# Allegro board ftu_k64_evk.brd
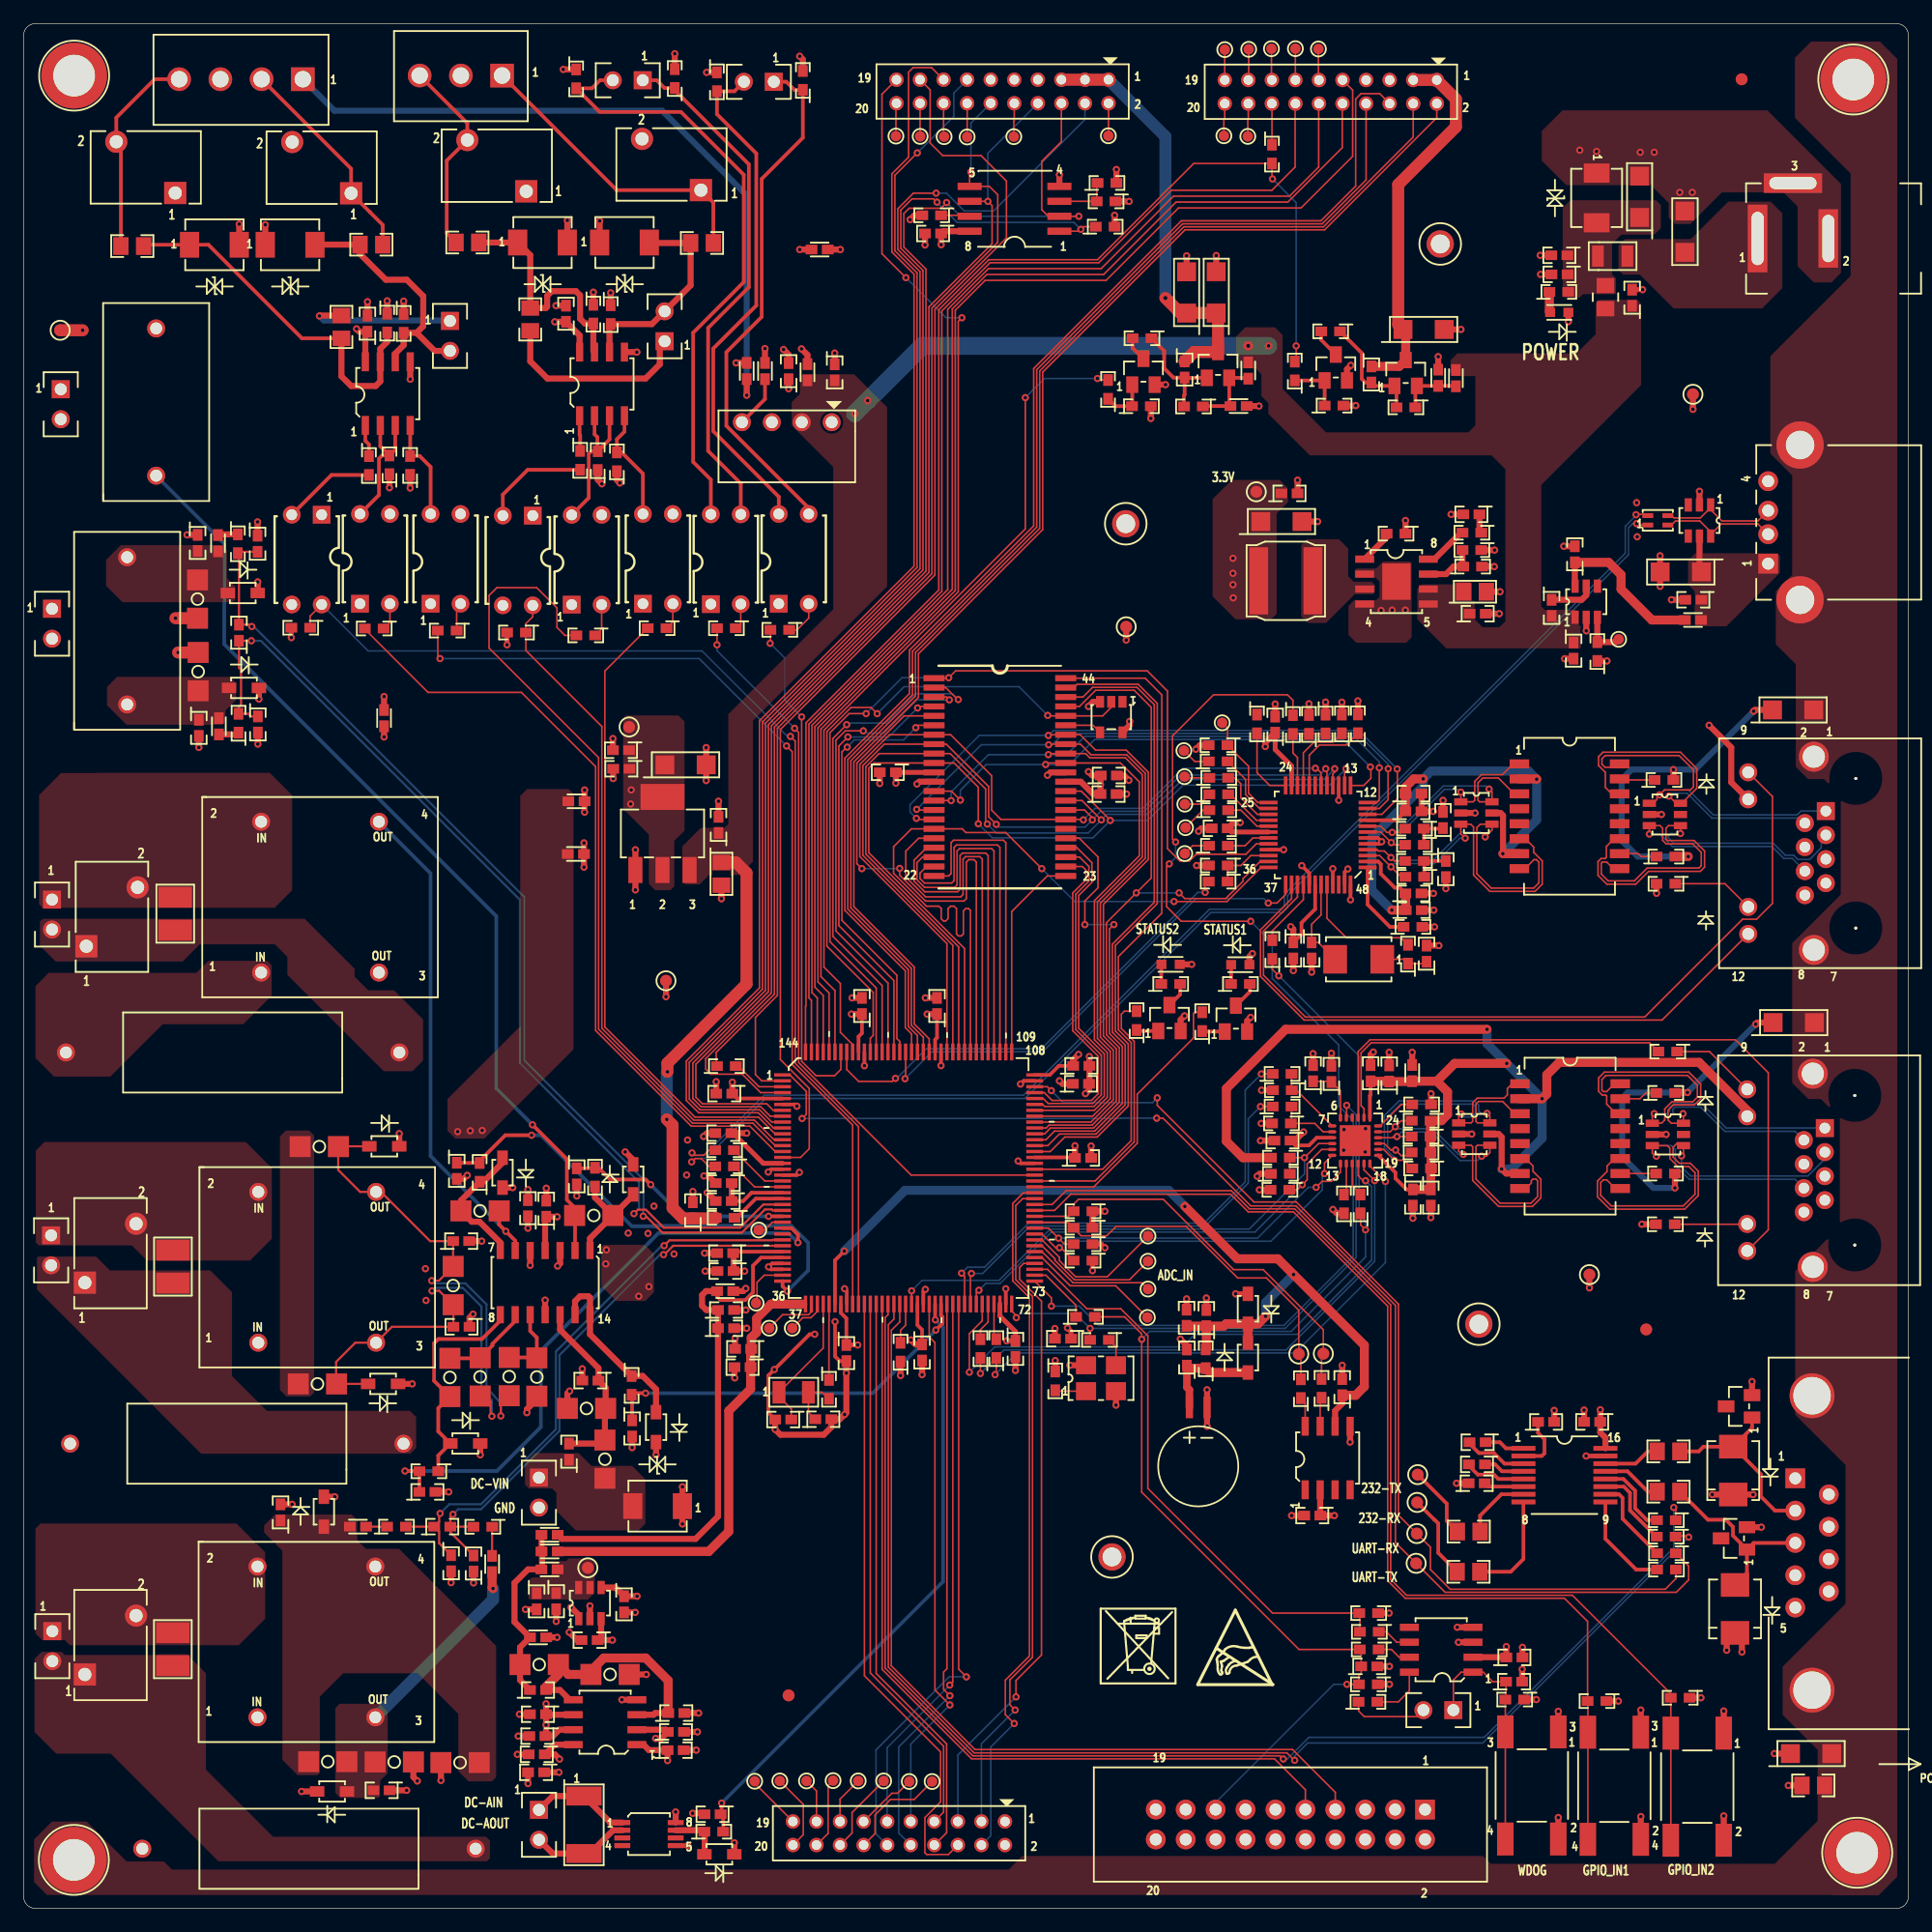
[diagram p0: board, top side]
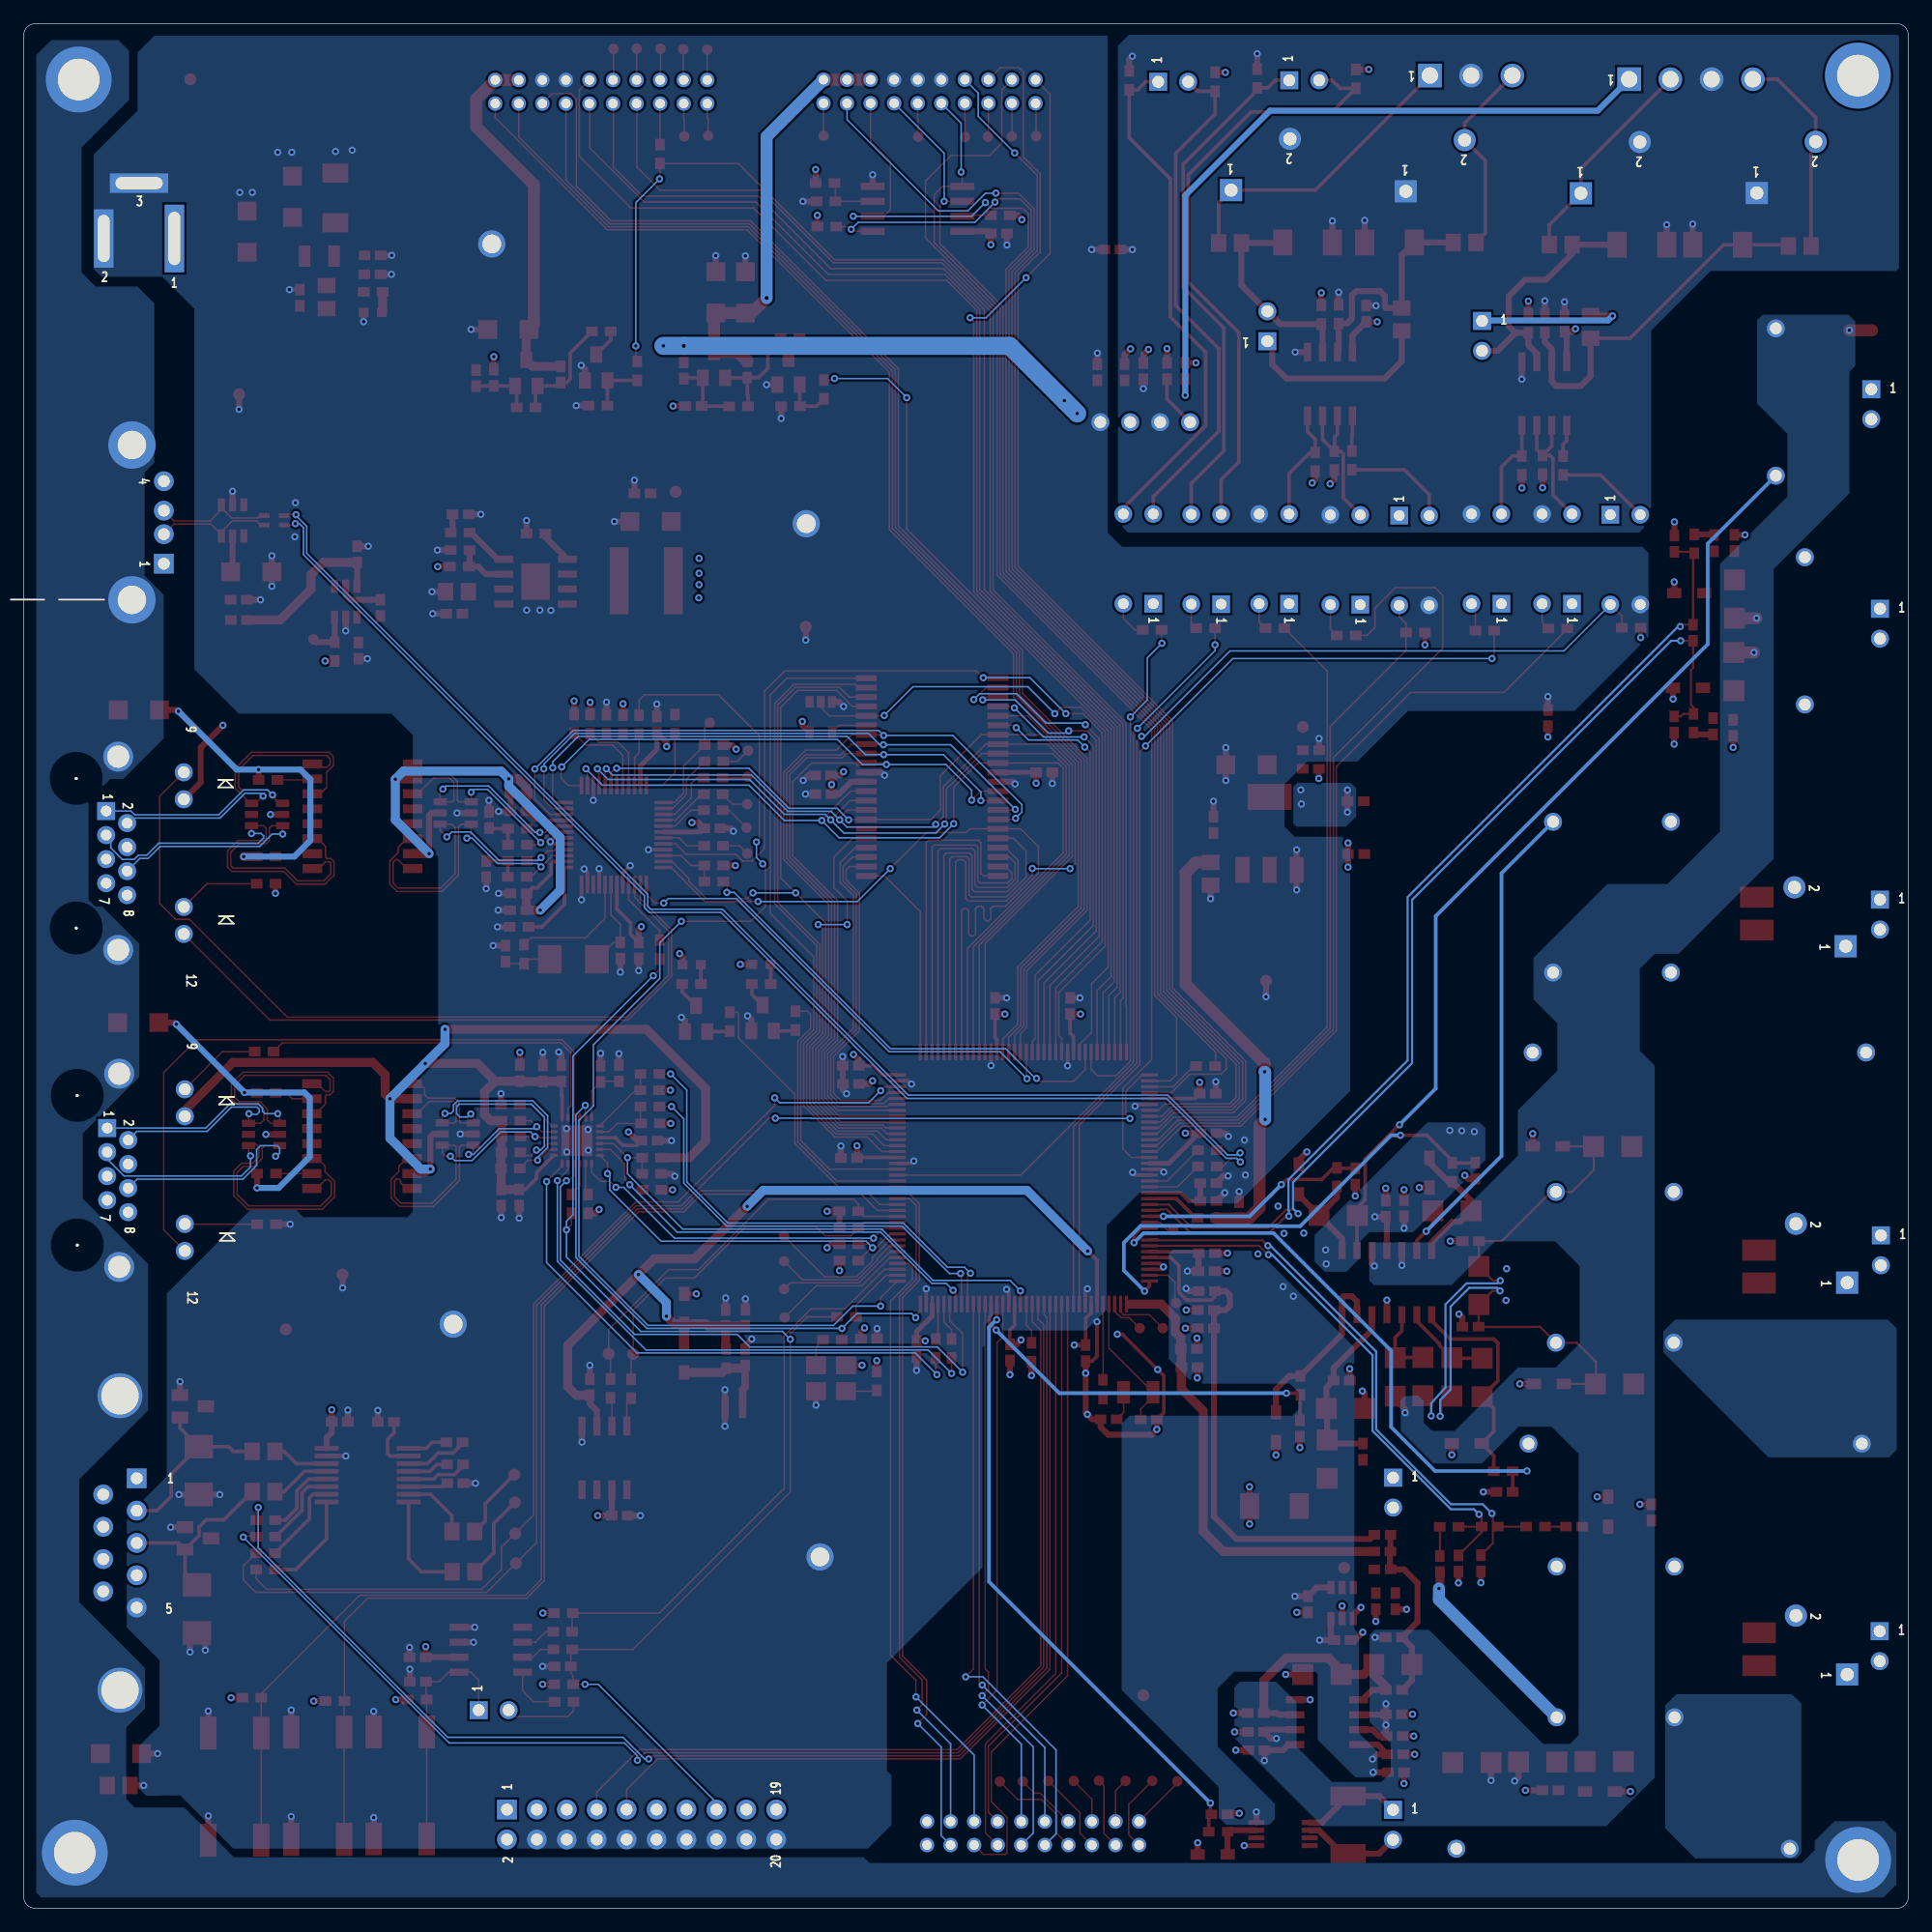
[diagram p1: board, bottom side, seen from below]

Outline 160 x 160 mm; copper layers: TOP, VCC, GND, BOTTOM. Coordinates in mm from the lower left corner of the outline.
Outline path: 0,158.98 0,1.02 arc(0.3,0.3) 1.02,0 158.98,0 arc(159.7,0.3) 160,1.02 160,158.98 arc(159.7,159.7) 158.98,160 1.02,160 arc(0.3,159.7) 0,158.98

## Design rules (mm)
net group AGND: nets N16923020 N16923054
net group DEBUG_RX: nets DEBUG_RX N16758843
net group DEBUG_TX: nets DEBUG_TX N16758837
net group DIFFPAIR0: nets ETH2_TXN ETH2_TXP
net group DIFFPAIR1: nets ETH2_RXN ETH2_RXP
net group DIFFPAIR2: nets ETH1_TXN ETH1_TXP
net group DIFFPAIR3: nets ETH1_RXN ETH1_RXP
net group DIFFPAIR4: nets ENET2_TX+ ENET2_TX-
net group DIFFPAIR5: nets ENET2_RX+ ENET2_RX-
net group DIFFPAIR6: nets ENET1_TX+ ENET1_TX-
net group DIFFPAIR7: nets ENET1_RX+ ENET1_RX-
net group DIFFPAIR8: nets USB_HOST_D_N USB_HOST_D_P
net group DIFFPAIR9: nets I2A_N I2A_P
net group DIFFPAIR11: nets U2_IN_L U2_IN_N
net group ENET_3V3A: nets ENET_3V3A RMII0_RXER
net group GPRS_PWR_CNTL: nets GPRS_PWR_CNTL N17042189
net group N16852593: nets N16852593 N16964483
net group RESET_B: nets N16852627 RESET_B
net group UART1_RX: nets N16997663 UART1_RX
net group UART1_TX: nets N16997666 UART1_TX
net group WDOG: nets N16852920 WDOG

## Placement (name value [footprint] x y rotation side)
BT1  MS621  [BAT_621]  99.71 40.93 180 top
C1  4.7UF  [CC0603]  89.76 70 0 top
C2  0.1UF  [CC0603]  77.54 76.61 90 top
C3  0.1UF  [CC0603]  71.17 76.61 90 top
C4  0.1UF  [CC0603]  89.94 63.7 0 top
C5  0.1UF  [CC0603]  59.48 69.16 180 top
C6  0.1UF  [CC0603]  69.84 47.14 270 top
C7  0.1UF  [CC0603]  59.41 65.81 180 top
C8  0.1UF  [CC0603]  89.78 71.53 0 top
C9  0.1UF  [CC0603]  76.27 47.19 270 top
C10  0.1UF  [CC0603]  84.2 47.5 270 top
C11  0.1UF  [CC0603]  61.08 47.5 180 top
C12  1.0UF  [CC0603]  61.03 45.95 180 top
C13  0.1UF  [CC0603]  59.63 49.25 0 top
C14  1.0UF  [CC0603]  59.63 50.8 0 top
C15  0.1UF  [CC0603]  59.56 55.63 180 top
C16  1.0UF  [CC0603]  59.58 54.1 180 top
C17  0.1UF  [CC0603]  59.43 61.57 180 top
C18  1.0UF  [CC0603]  59.43 60.05 180 top
C19  0.1UF  [CC0603]  56.81 59.26 90 top
C20  5.6PF  [CC0603]  64.49 41.5 180 top
C21  5.6PF  [CC0603]  67.89 41.53 0 top
C22  0.1UF  [CC0603]  109.39 33.35 180 top
C23  0.1UF  [CC0603]  111.93 44.25 90 top
C24  1.0UF  [CC0603]  100.4 50.11 90 top
C25  0.1UF  [CC0603]  98.72 50.14 90 top
C26  0.1UF  [CC0603]  88.23 48.36 180 top
C27  0.1UF  [CC0603]  98.75 46.76 90 top
C28  4.7UF  [CC0603]  73.36 96.44 180 top
C29  0.1UF  [CC0603]  92.1 94.6 0 top
C30  0.1UF  [CC0603]  92.13 96.17 0 top
C31  0.1UF  [CC0603]  77.21 142.18 180 top
C32  1.0UF  [CC0603]  44.37 59.4 90 top
C33  0.1UF  [CC0603]  42.81 59.44 90 top
C34  3300PF  [CC0603]  46.96 62.14 270 top
C35  0.01UF  [CC0603]  14.88 100.22 270 top
C36  3300PF  [CC0603]  19.89 100.5 270 top
C37  1000PF  [CC0603]  18.28 108.29 90 top
C38  0.01UF  [CC0603]  14.78 115.91 270 top
C39  3300PF  [CC0603]  36.77 62.61 270 top
C40  3300PF  [CC0603]  19.86 115.84 270 top
C41  4700pF  [CC1210]  12.87 84.44 90 top
C42  3300PF  [CC0603]  34.28 35.36 0 top
C43  0.01UF  [CC0603]  37.15 56.65 0 top
C44  4700pF  [CC1210]  12.68 54.48 90 top
C45  0.01UF  [CC0603]  37.17 49.37 180 top
C46  0.01UF  [CC0603]  46.3 38.77 90 top
C47  0.01UF  [CC0603]  48.11 44.81 180 top
C48  3300PF  [CC0603]  51.66 40.75 270 top
C49  0.01UF  [CC0603]  21.81 33.62 90 top
C50  3300PF  [CC0603]  36.29 29.3 270 top
C51  4700pF  [CC1210]  12.67 22.01 90 top
C52  1000PF  [CC0603]  35.54 32.41 0 top
C53  0.01UF  [CC0603]  30.39 10.03 180 top
C54  3300PF  [CC0603]  38.2 29.28 90 top
C55  3300PF  [CC0603]  58.49 7.99 180 top
C56  1.0UF  [CC0603]  50.97 25.82 270 top
C57  0.1UF  [CC0603]  48.05 22.78 180 top
C58  1.0UF  [CC0603]  43.55 26.07 270 top
C59  0.1UF  [CC0603]  45.21 26.08 270 top
C60  4.7UF  [CC0603]  115.92 70.88 90 top
C61  0.1UF  [CC0603]  119.46 60.35 270 top
C62  0.1UF  [CC0603]  106.87 65.18 180 top
C63  0.1UF  [CC0603]  117.93 60.35 270 top
C64  0.1UF  [CC0603]  114.35 70.9 90 top
C65  1000PF  [CC1206]  150.26 75.2 0 top
C66  1000PF  [CC1206]  151.73 13.14 0 top
C67  1.0UF  [CC0603]  111.02 70.84 90 top
C68  0.1UF  [CC0603]  109.46 70.9 90 top
C69  4.7UF  [CC0603]  107.79 81.32 270 top
C70  0.1UF  [CC0603]  106.24 100.49 90 top
C71  0.1UF  [CC0603]  101.54 91.69 180 top
C72  4.7UF  [CC0603]  117.99 94.63 0 top
C73  0.1UF  [CC0603]  117.98 93.12 0 top
C74  0.1UF  [CC0603]  118.01 84.74 0 top
C75  0.1UF  [CC0603]  117.98 86.16 0 top
C76  1000PF  [CC1206]  150.21 101.74 0 top
C77  8PF  [CC0603]  119.1 81.05 90 top
C78  8PF  [CC0603]  109.34 81.32 270 top
C80  100uF  [CC1206]  140.67 113.45 180 top
C81  2.2uF  [CC0603]  141.74 111.09 180 top
C82  2.2uF  [CC0603]  131.58 106.77 270 top
C83  1000PF  [CC0603]  129.71 110.4 270 top
C84  2.2uF  [CC0603]  131.68 114.95 90 top
C85  0.1UF  [CC0603]  29.19 134.53 90 top
C86  0.1UF  [CC0603]  68.85 130.39 270 top
C87  0.1UF  [CC0603]  64.94 130.49 90 top
C88  0.1UF  [CC0603]  46.05 135.37 90 top
C89  0.1UF  [CC0603]  129.24 41.3 0 top
C90  0.1UF  [CC0603]  133.15 41.3 180 top
C91  0.1UF  [CC0603]  123.35 36.09 0 top
C92  0.1UF  [CC0603]  123.38 37.69 180 top
C93  0.1UF  [CC0603]  123.43 39.57 180 top
C95  0.1UF  [CC0603]  126.52 19.25 0 top
C96  0.1UF  [CC0603]  126.55 21.31 0 top
C97  0.1UF  [CC0603]  114.23 20.55 0 top
C98  100uF  [CC1206]  98.73 137.18 90 top
C99  100uF  [CC1206]  101.24 137.18 90 top
C100  0.1UF  [CC0603]  98.56 130.63 270 top
C101  100uF  [CC1206]  118.84 134.03 0 top
C102  0.1UF  [CC0603]  114.41 130.21 270 top
C103  100uF  [CC1206]  137.18 145.3 90 top
C104  1.0UF  [CC0603]  130.38 138.71 180 top
C105  0.1UF  [CC0603]  130.37 140.33 180 top
C106  0.1UF  [CC0603]  136.55 136.73 90 top
C107  10UF  [CC0805]  123.21 111.77 0 top
C108  0.1UF  [CC0603]  123.44 109.91 0 top
C109  47uF  [CC1206]  106.78 117.73 0 top
C110  0.1UF  [CC0603]  107.46 120.12 0 top
C111  470pF  [CC0603]  122.9 118.34 180 top
C112  10UF  [CC0805]  59.24 87.83 270 top
C113  0.1UF  [CC0603]  58.99 91.98 90 top
C114  47uF  [CC1206]  56.19 97.08 0 top
C115  0.1UF  [CC0603]  50.74 96.74 180 top
C116  0.1UF  [CC0603]  50.71 98.32 180 top
C117  0.1UF  [CC0603]  43.56 13.08 180 top
C118  1.0UF  [CC0603]  43.51 11.56 180 top
C119  0.1UF  [CC0603]  43.67 16.48 180 top
C120  1.0UF  [CC0603]  55.38 14.99 0 top
C121  0.1UF  [CC0603]  55.35 13.44 0 top
C122  1.0UF  [CC0603]  43.61 14.63 180 top
C123  0.1UF  [CC0603]  43.67 18.54 0 top
C124  0.1UF  [CC0603]  55.41 16.59 0 top
C125  0.1UF  [CC0603]  120.49 92.39 90 top
C126  0.1UF  [CC0603]  120.73 88.23 270 top
CT1  TR2155-2C 5A:2.5mA  [CT_2A]  11.26 127.87 90 top
CT2  TR2155-2C 5A:2.5mA  [CT_2A]  8.79 108.45 90 top
D1  NSR0320  [SOD323]  103.93 50.9 0 top
D2  NSR0320  [SOD323]  103.93 46.76 180 top
D3  PESD3V3L1BA  [SOD323]  51.75 61.89 180 top
D4  PESD3V3L1BA  [SOD323]  40.66 62.46 0 top
D5  PESD3V3L1BA  [SOD323]  37.5 39.47 90 top
D6  PESD3V3L1BA  [SOD323]  53.69 40.86 0 top
D7  PESD3V3L1BA  [SOD323]  59.06 4.6 90 top
D8  RED  [LED_0603]  103.29 80.11 180 top
D9  RED  [LED_0603]  97.37 80.14 180 top
D10  SMP100LC-25  [DO-214AA]  145.28 25.43 90 top
D11  SMP100LC-25  [DO-214AA]  145.13 37.17 90 top
D12  LED_GREEN  [LED_0603]  130.36 135.48 0 top
D13  PESD3V3L1BA  [SOD323]  18.71 103.61 90 top
D14  PESD3V3L1BA  [SOD323]  18.61 111.66 90 top
D15  PESD3V3L1BA  [SOD323]  30.62 64.7 90 top
D16  PESD3V3L1BA  [SOD323]  30.52 44.53 90 top
D17  PESD3V3L1BA  [SOD323]  26.19 9.93 270 top
D18  PESD3V3L1BA  [SOD323]  25.49 33.68 180 top
DN1  ESDA14V2L  [SOT-23]  145.19 31.41 90 top
DN2  ESDA14V2L  [SOT-23]  145.62 42.62 90 top
F1  5A/32V  [FUSE_3P4X1P8]  134.89 140.26 180 top
J1  HDR 1X2  [HDR102]  3.16 128.96 0 top
J2  HDR 1X2  [HDR102]  2.42 110.32 0 top
J3  HDR 1X2  [HDR102]  2.42 85.64 0 top
J4  HDR 1X2  [HDR102]  2.34 57.14 0 top
J5  HDR 1X2  [HDR102]  43.75 36.57 0 top
J6  HDR 1X2  [HDR102]  43.75 8.37 0 top
J7  HDR 1X2  [HDR102]  2.44 23.53 0 top
J8  HDR 1X2  [HDR102]  52.56 155.19 270 top
J9  HDR 1X2  [HDR102]  63.68 155.06 270 top
J10  Female HDR_2X10_2MM  [HDR210_2MM]  74.31 6.38 180 top
J11  USB_TYPE_A  [USB_A]  148.09 114.15 90 top
J12  HDR 1X2  [HDR102]  36.2 134.76 0 top
J13  TB_1X4  [CON4_3P5_14P5X7MM]  23.71 155.28 180 top
J14  HDR 1X2  [HDR102]  54.42 133.03 180 top
J15  TB_1X3  [CON3_3P5_11X7MM]  40.62 155.59 180 top
J16  DB9  [CON_DB9S_RA_318]  150.39 36.51 0 top
J17  HDR 1X2  [HDR102]  121.37 16.83 270 top
J18  HDR 2X10  [HDR_2X10]  118.97 8.39 270 top
J21  Female HDR_2X10_2MM  [HDR210_2MM]  83.1 154.24 180 top
J22  Female HDR_2X10_2MM  [HDR210_2MM]  110.96 154.21 180 top
L1  120OHM  [IND_0603]  59.56 52.4 0 top
L2  120OHM  [IND_0603]  30.6 101.04 90 top
L3  120OHM  [IND_0603]  46.88 89.51 0 top
L4  120OHM  [IND_0603]  46.93 93.98 0 top
L5  120OHM  [IND_0603]  16.58 100.35 270 top
L6  120OHM  [IND_0603]  16.51 115.89 90 top
L7  120OHM  [IND_0603]  28.39 32.41 0 top
L8  120OHM  [IND_0603]  39.77 29.23 90 top
L9  120OHM  [IND_0603]  44.66 30.3 180 top
L10  120OHM  [IND_0603]  44.65 28.78 180 top
L11  120OHM  [IND_0603]  117.88 70.91 270 top
L12  120OHM  [IND_0603]  141.71 109.37 0 top
L14  90OHM  [IND4_CHOKE_0805]  138.72 117.83 0 top
L15  120OHM  [IND_0603]  62.94 130.5 90 top
L16  120OHM  [IND_0603]  66.54 130.4 90 top
L17  120OHM  [IND_0603]  61.39 130.51 90 top
L18  120OHM  [IND_0603]  67.58 140.82 180 top
L20  120OHM  [IND_0603]  103.14 127.53 0 top
L21  120OHM  [IND_0603]  120.08 129.93 90 top
L22  120OHM  [IND_0603]  103.96 130.55 90 top
L23  120OHM  [IND_0603]  121.58 129.9 90 top
L24  60ohm  [IND_0805]  134.28 136.78 270 top
L25  2.2uH  [IND2_6P3X6P3]  107.15 112.7 180 top
L26  120OHM  [IND_0603]  43.68 23.01 180 top
L27  120OHM  [IND_0603]  44.65 31.72 180 top
NOREF  -  []  65.13 52 0 top
NOREF#2  -  []  20.33 139.24 0 top
NOREF#3  -  []  91.43 19.1 0 top
NOREF#4  -  []  110.98 63.12 0 top
NOREF#5  -  [unnamed#2]  145.84 155.27 0 top
NOREF#6  -  []  93.98 29.84 0 top
NOREF#7  -  []  0 155.61 0 top
NOREF#8  -  []  -355.73 203.96 0 top
NOREF#9  -  []  105.68 88.37 0 top
NOREF#10  -  []  127.55 86.23 0 top
NOREF#11  -  []  107.14 86.92 0 top
NOREF#12  -  []  20.52 141.22 0 top
NOREF#13  -  []  95.15 117.54 0 top
NOREF#14  -  []  66.38 51.3 90 top
NOREF#15  -  []  111.79 63.22 0 top
NOREF#16  -  []  113.79 63.22 0 top
NOREF#17  -  []  121.84 141.29 0 top
NOREF#18  -  []  -404.37 -311.53 0 top
NOREF#19  -  []  -74.1 -230.2 0 top
NOREF#20  -  []  41.94 141.41 0 top
NOREF#21  -  []  135.53 68.73 90 top
NOREF#22  -  []  48.71 139.43 0 top
NOREF#23  -  []  70.38 51.3 0 top
NOREF#24  -  []  135.53 61.11 90 top
NOREF#25  -  []  107.14 86.92 90 top
NOREF#26  -  []  111.08 63.93 90 top
NOREF#27  -  []  41.75 139.43 0 top
NOREF#28  -  []  6.6 -66.29 0 top
NOREF#29  -  []  85.13 52 90 top
NOREF#30  -  []  135.48 95.89 90 top
NOREF#31  -  []  114.09 93.37 90 top
NOREF#32  -  []  133.53 143.09 90 top
NOREF#33  -  []  -232.21 -153.95 0 top
NOREF#34  -  []  134.91 86.23 90 top
NOREF#35  -  []  64.43 53.25 0 top
NOREF#36  -  []  131.55 142.9 90 top
NOREF#37  -  []  15.32 0 90 top
NOREF#38  -  []  99.69 19 0 top
NOREF#39  -  []  127.6 59.08 0 top
NOREF#40  -  [unnamed#2]  137.74 49.15 0 top
NOREF#41  -  []  106.38 87.62 90 top
NOREF#42  -  [unnamed#2]  64.94 18.08 0 top
NOREF#43  -  []  14.09 141.22 0 top
NOREF#44  -  []  110.98 63.12 90 top
NOREF#45  -  []  48.9 141.41 0 top
NOREF#46  -  []  125.12 49.6 0 top
NOREF#47  -  []  111.08 63.93 90 top
NOREF#48  -  []  135.48 88.27 90 top
NOREF#49  -  []  134.96 59.08 90 top
NOREF#50  -  []  51.52 36.13 0 top
NOREF#51  -  []  13.9 139.24 0 top
NOREF#52  -  []  51.71 34.15 0 top
NOREF#53  -  []  106.38 94.63 0 top
NOREF#54  -  []  70.99 -21.34 180 bottom
NOREF#55  -  []  72.26 -25.27 180 bottom
NOREF#56  -  []  59.05 -22.99 180 bottom
NOREF#57  -  []  50.03 -19.56 180 bottom
NOREF#58  -  []  57.14 -30.23 180 bottom
NOREF#59  -  []  51.56 -26.42 180 bottom
P1  CONN RJ45 8  [CON8_RJ45_LED_JACK]  152.9 66.24 90 top
P2  CONN RJ45 8  [CON8_RJ45_LED_JACK]  152.99 93.15 90 top
P3  CONN PWR 1  [PJ-202B]  147.2 141.76 0 top
PT1  TR3121 2.5mA:2.5mA  [PT_4P]  25.17 85.84 0 top
PT2  TR3121 2.5mA:2.5mA  [PT_4P]  24.92 54.42 0 top
PT3  TR3121 2.5mA:2.5mA  [PT_4P]  24.86 22.62 0 top
Q1  MMBT3904LT1G  [SOT-23]  102.91 75.53 0 top
Q2  MMBT3904LT1G  [SOT-23]  97.27 75.58 0 top
Q3  AO3415  [SOT-23]  101.4 131.03 0 top
Q4  AO3415  [SOT-23]  117.32 130.34 0 top
Q5  2N7002  [SOT-23]  95.06 130.45 0 top
Q6  2N7002  [SOT-23]  111.39 130.8 0 top
QZ1  32.768KHZ  [XTAL2-3P2X1P5-SM]  65.37 43.81 0 top
R1  10.0K  [RC0603]  74.44 47.22 90 top
R2  22  [RC0603]  81.22 47.52 90 top
R3  0  [RC0603]  59.56 58.62 180 top
R4  22  [RC0603]  82.57 47.52 90 top
R5  4.7K  [RC0603]  89.94 59.18 180 top
R6  4.7K  [RC0603]  89.94 57.78 180 top
R7  4.7K  [RC0603]  89.94 56.39 180 top
R8  4.7K  [RC0603]  89.94 54.99 180 top
R9  22  [RC0603]  59.51 64.36 180 top
R10  22  [RC0603]  59.51 62.99 180 top
R11  0  [RC0603]  90.14 50.22 0 top
R12  22  [RC0603]  68.37 44.07 270 top
R13  22  [RC0603]  59.66 71.5 0 top
R14  0  [RC0603]  108.43 44.12 90 top
R15  0  [RC0603]  110.18 44.15 90 top
R16  10.0K  [RC0603]  87.57 44.78 270 top
R17  1K  [RC0603]  100.35 46.66 90 top
R18  22  [RC0603]  91.33 48.26 180 top
R23  10.0K  [RC0603]  91.97 146.47 0 top
R24  10.0K  [RC0603]  91.82 142.76 0 top
R25  10.0K  [RC0603]  77.09 143.73 180 top
R26  10.0K  [RC0603]  91.89 144.91 180 top
R27  100  [RC0603]  48.51 62.07 90 top
R28  200  [RC_MELF_0204]  48.4 58.82 0 top
R29  100  [RC0603]  18.25 100.61 90 top
R30  100  [RC_MELF_0204]  14.82 104.99 90 top
R31  100  [RC0603]  38.72 62.48 90 top
R32  100  [RC_MELF_0204]  14.77 111.15 90 top
R33  200  [RC_MELF_0204]  38.75 59.21 180 top
R34  100  [RC0603]  18.19 115.84 270 top
R35  11K  [RC_MELF_0204]  43.57 45.11 90 top
R36  EE1/2 160K BC3  [RES_TH]  17.75 72.66 180 top
R37  10K  [RC_MELF_0204]  41.22 45.15 90 top
R38  100  [RC0603]  34.4 37.11 180 top
R39  10K  [RC_MELF_0204]  38.76 45.12 90 top
R40  11K  [RC_MELF_0204]  36.19 45.07 270 top
R41  EE1/2 160K BC3  [RES_TH]  18.1 39.45 180 top
R42  200  [RC_MELF_0204]  25.11 64.67 180 top
R43  680  [RC_MELF_0204]  36.47 52.87 270 top
R44  200  [RC_MELF_0204]  24.95 44.52 0 top
R45  100K  [RC_MELF_0204]  49.35 38.14 90 top
R46  100  [RC0603]  51.62 44.4 270 top
R47  2K  [RC_MELF_0204]  47.79 42.44 180 top
R48  0.5  [RC2010]  47.57 7.1 270 top
R49  100  [RC0603]  31.66 32.41 0 top
R50  EE1/2 160K BC3  [RES_TH]  24.23 5.07 180 top
R51  200  [RC_MELF_0204]  37.05 12.38 180 top
R52  680  [RC_MELF_0204]  25.82 12.46 0 top
R53  200  [RC_MELF_0204]  31.47 12.43 180 top
R54  100  [RC0603]  38.99 32.4 180 top
R55  100  [RC0603]  58.59 6.51 0 top
R56  10.0K  [RC0603]  106.78 66.64 180 top
R57  10.0K  [RC0603]  106.86 69.46 180 top
R58  10.0K  [RC0603]  106.65 61 180 top
R59  49.9  [RC0603]  118.64 66.87 180 top
R60  49.9  [RC0603]  118.63 65.52 180 top
R61  49.9  [RC0603]  118.63 64.18 180 top
R62  49.9  [RC0603]  118.68 62.82 180 top
R63  22  [RC0603]  106.83 68.07 0 top
R64  22  [RC0603]  106.83 70.84 0 top
R65  75.0  [RC0603]  139.38 62.38 0 top
R66  75.0  [RC0603]  139.4 69.23 0 top
R67  470  [RC0603]  139.37 58.08 180 top
R68  470  [RC0603]  139.57 72.73 180 top
R69  0  [RC0603]  113.5 59.8 90 top
R70  0  [RC0603]  106.69 63.73 180 top
R71  10.0K  [RC0603]  112.09 59.8 90 top
R72  0  [RC0805]  151.92 10.44 0 top
R73  12.1K  [RC0603]  118.68 68.25 0 top
R74  10.0K  [RC0603]  106.69 62.36 0 top
R75  49.9  [RC0603]  118.07 90.29 180 top
R76  49.9  [RC0603]  118.07 91.66 180 top
R77  49.9  [RC0603]  118.1 87.57 180 top
R78  49.9  [RC0603]  118.07 88.92 180 top
R79  10.0K  [RC0603]  111.91 100.55 90 top
R80  10.0K  [RC0603]  113.27 100.56 90 top
R81  10.0K  [RC0603]  109.11 100.5 90 top
R82  10.0K  [RC0603]  101.39 98.74 180 top
R83  10.0K  [RC0603]  101.42 88.53 180 top
R84  0  [RC0603]  101.43 90.21 0 top
R85  0  [RC0603]  101.45 93.23 0 top
R86  0  [RC0603]  101.45 94.57 0 top
R87  0  [RC0603]  101.45 95.97 0 top
R88  10.0K  [RC0603]  110.52 100.54 270 top
R89  0  [RC0603]  101.4 97.37 0 top
R90  0  [RC0603]  104.7 100.55 270 top
R91  0  [RC0603]  107.75 100.5 270 top
R92  75.0  [RC0603]  139.42 89.29 0 top
R93  75.0  [RC0603]  139.25 95.79 0 top
R94  470  [RC0603]  139.42 86.98 180 top
R95  0  [RC0603]  101.4 87.16 180 top
R96  22  [RC0603]  117.52 81.01 90 top
R97  6.80K  [RC0603]  117.94 83.32 0 top
R98  0  [RC0603]  106 81.39 90 top
R99  470  [RC0603]  103.29 78.47 0 top
R100  470  [RC0603]  97.38 78.47 0 top
R101  1K  [RC0603]  100.05 75.28 90 top
R102  1K  [RC0603]  94.49 75.37 90 top
R103  4.7K  [RC0603]  58.86 155.05 270 top
R104  4.7K  [RC0603]  46.91 155.3 270 top
R105  1K  [RC0603]  64.19 108.54 180 top
R106  1K  [RC0603]  59.66 108.67 180 top
R107  0  [RC0603]  66.15 155.17 90 top
R108  0  [RC0603]  55.28 155.33 90 top
R109  10.0K  [RC0603]  133.56 17.6 180 top
R110  10.0K  [RC0603]  140.62 17.88 180 top
R111  10.0K  [RC0603]  133.59 106.69 90 top
R112  4.7K  [RC0603]  23.53 108.71 180 top
R113  1K  [RC0603]  29.32 122.48 270 top
R114  4.7K  [RC0603]  31.06 122.54 90 top
R115  1K  [RC0603]  29.77 108.65 180 top
R116  1K  [RC0603]  32.26 134.55 270 top
R117  1K  [RC0603]  30.87 134.57 270 top
R118  4.7K  [RC0603]  32.81 122.49 90 top
R119  1K  [RC0603]  35.96 108.47 180 top
R120  4.7K  [RC0603]  41.84 108.31 180 top
R121  1K  [RC0603]  47.25 122.92 270 top
R122  10  [RC0805]  29.52 141.23 0 top
R123  4.7K  [RC0603]  48.74 122.9 90 top
R124  120  [RC0805]  26.98 134.25 270 top
R125  1K  [RC0603]  47.72 108.06 180 top
R126  1K  [RC0603]  49.84 135.29 270 top
R127  1K  [RC0603]  48.37 135.33 270 top
R128  10  [RC0805]  9.23 141.11 180 top
R129  10  [RC0805]  57.59 141.37 0 top
R130  4.7K  [RC0603]  50.36 122.8 90 top
R131  1K  [RC0603]  53.78 108.68 180 top
R132  120  [RC0805]  43.01 134.89 90 top
R133  10  [RC0805]  37.67 141.42 180 top
R134  0  [RC0603]  139.44 31.56 180 top
R135  10  [RC0805]  139.63 38.8 0 top
R136  0  [RC0603]  139.46 30.15 180 top
R137  10  [RC0805]  122.67 31.99 180 top
R138  0  [RC0603]  139.45 32.96 180 top
R139  10  [RC0805]  139.63 35.38 0 top
R140  0  [RC0603]  139.46 28.77 180 top
R141  10  [RC0805]  122.65 28.58 180 top
R142  10.0K  [RC0603]  126.58 17.73 180 top
R143  0  [RC0603]  114.12 17.54 0 top
R144  10.0K  [RC0603]  114.16 19.03 180 top
R145  10.0K  [RC0603]  114.18 25.07 180 top
R146  0  [RC0603]  114.23 21.98 180 top
R147  0  [RC0603]  114.24 23.48 180 top
R148  0  [RC0603]  105.97 148.92 270 top
R149  100K  [RC0603]  99.31 127.5 180 top
R150  100K  [RC0603]  117.34 127.42 180 top
R151  470  [RC0603]  94.94 133.29 180 top
R152  470  [RC0603]  110.95 133.87 180 top
R153  1K  [RC0603]  92.06 128.94 90 top
R154  1K  [RC0603]  107.91 130.51 90 top
R155  10.0K  [RC0603]  94.89 127.52 0 top
R156  10.0K  [RC0603]  111.24 127.57 0 top
R157  1K  [RC0603]  130.32 137.22 0 top
R158  75K  [RC0603]  123.01 113.9 0 top
R159  180K  [RC0603]  116.5 116.7 180 top
R160  30K  [RC0603]  122.94 116.78 180 top
R161  24K  [RC0603]  122.94 115.31 180 top
R162  10K  [RC_MELF_0204]  43.77 20.7 0 top
R163  10K  [RC_MELF_0204]  49.79 19.86 0 top
SS1  .635" LONG  [SPACER_139T]  4.29 155.58 0 top
SS2  .635" LONG  [SPACER_139T]  4.27 4.12 0 top
SS3  .635" LONG  [SPACER_139T]  155.65 4.73 0 top
SS4  .635" LONG  [SPACER_139T]  155.32 155.25 0 top
SW1  SPST PB  [SW4_PB_ESW_SM_P177]  135.03 10.41 0 top
SW2  SPST PB  [SW4_PB_ESW_SM_P177]  142.07 10.34 0 top
SW3  SPST PB  [SW4_PB_ESW_SM_P177]  128.03 10.44 0 top
T1  H1102NL  [H1102_XFMR16_SM]  131.28 65.56 0 top
T2  H1102NL  [H1102_XFMR16_SM]  131.23 92.71 0 top
TP1  TEST POINT  [C035S]  95.4 50.16 0 top
TP2  TEST POINT  [C035S]  95.45 52.58 0 top
TP3  TEST POINT  [C035S]  95.45 54.94 0 top
TP4  TEST POINT  [C035S]  95.45 57.07 0 top
TP5  -  [TPAD_040]  110.33 47.09 90 top
TP6  -  [TPAD_040]  108.25 47.07 180 top
TP7  -  [TPAD_040]  47.9 28.92 0 top
TP8  TEST POINT  [C035S]  98.57 93.74 0 top
TP9  TEST POINT  [C035S]  98.57 89.55 0 top
TP10  TEST POINT  [C035S]  98.63 91.74 0 top
TP11  TEST POINT  [C035S]  98.55 96.07 0 top
TP12  TEST POINT  [C035S]  98.5 98.28 0 top
TP13  TEST POINT  [C035S]  101.75 100.65 0 top
TP17  TEST POINT  [C035S]  77.12 10.77 180 top
TP18  TEST POINT  [C035S]  70.85 10.82 180 top
TP19  TEST POINT  [C035S]  73.01 10.82 180 top
TP20  TEST POINT  [C035S]  135.4 107.73 0 top
TP21  -  [TPAD_040]  118.21 29.3 90 top
TP22  -  [TPAD_040]  118.27 31.82 0 top
TP23  -  [TPAD_040]  118.34 36.83 0 top
TP24  -  [TPAD_040]  118.29 34.46 0 top
TP25  TEST POINT  [C035S]  92.09 150.47 180 top
TP26  TEST POINT  [C035S]  84.06 150.4 180 top
TP27  TEST POINT  [C035S]  109.92 157.84 180 top
TP28  TEST POINT  [C035S]  107.96 157.87 180 top
TP29  TEST POINT  [C035S]  80.1 150.37 180 top
TP30  TEST POINT  [C035S]  105.93 157.87 180 top
TP31  TEST POINT  [C035S]  78.14 150.4 180 top
TP32  -  [TPAD_040]  104.64 120.25 0 top
TP33  -  [TPAD_040]  51.4 100.29 0 top
TP34  TEST POINT  [C035S]  104 157.81 180 top
TP35  TEST POINT  [C035S]  101.97 157.79 180 top
TP36  TEST POINT  [C035S]  103.92 150.42 180 top
TP37  TEST POINT  [C035S]  101.89 150.47 180 top
TP38  TEST POINT  [C035S]  76.11 150.42 180 top
TP39  TEST POINT  [C035S]  74.05 150.45 180 top
TP40  TEST POINT  [C035S]  66.46 10.82 180 top
TP41  TEST POINT  [C035S]  62.06 10.8 180 top
TP42  TEST POINT  [C035S]  68.72 10.85 180 top
TP43  TEST POINT  [C035S]  64.2 10.82 180 top
TP44  -  [TPAD_040]  3.11 133.96 0 top
TP45  TEST POINT  [C035S]  75.18 10.77 0 top
TP46  TEST POINT  [C035S]  63.3 49.26 0 top
TP47  TEST POINT  [C035S]  65.25 49.26 0 top
TP48  TEST POINT  [C035S]  62.18 51.39 0 top
TP49  TEST POINT  [C035S]  62.41 57.59 0 top
TP_GND1  TESTLOOP_BLACK  [TP_TH_063]  93.56 117.54 0 top
TP_GND2  TESTLOOP_BLACK  [TP_TH_063]  120.26 141.29 0 top
TP_GND3  TESTLOOP_BLACK  [TP_TH_063]  92.39 29.84 0 top
TP_GND4  TESTLOOP_BLACK  [TP_TH_063]  123.53 49.6 0 top
TP_GND5  -  [TPAD_040]  93.6 108.79 0 top
TP_GND6  -  [TPAD_040]  54.53 78.75 0 top
TP_GND7  -  [TPAD_040]  141.71 128.53 0 top
TP_GND8  -  [TPAD_040]  132.92 53.8 0 top
TVS1  SMBJ60CA  [DO-214AA_BIDIR]  53.82 34.15 180 top
TVS2  SMBJ6.0CA  [DO-214AA_BIDIR]  22.63 141.22 0 top
TVS3  SMBJ6.0CA  [DO-214AA_BIDIR]  16.2 141.22 0 top
TVS4  SMBJ6.0CA  [DO-214AA_BIDIR]  51.01 141.41 0 top
TVS5  SMBJ6.0CA  [DO-214AA_BIDIR]  44.05 141.41 0 top
TVS6  SMBJ6.0CA  [DO-214AA_BIDIR]  133.53 145.2 270 top
U1  MK64FN1M0VLQ12  [LQFP144_0P5_20X20MM]  75.13 62 0 top
U2  DS3231MZ  [SO8_1P27_4X5]  110.7 38.24 90 top
U3  IS61LV25616AL-10TLI  [TSOP44_T2]  82.87 96.04 0 top
U4  SN74LVC1G04  [SOT-23-5]  92.33 101.13 180 top
U5  W25Q64BVSSIG  [SO8WST]  84.12 144.28 180 top
U6  MCP6004-I/SL  [SOIC14_1P27_4X8]  44.27 53.12 270 top
U7  MAX44285TAUA+  [MSOP08_0P65_3P2X3P2]  53.09 6.31 0 top
U8  ADR3412ARJZ-R2  [SOT23-6]  48.08 25.92 0 top
U9  SRV05-4  [SOT23-6]  123.15 65.74 270 top
U10  SRV05-4  [SOT23-6]  139.58 65.7 270 top
U11  LAN8720A  [QFN24_4X4MM_SLUG]  113.04 65.18 180 top
U12  DM9000A  [LQFP48]  109.89 91.12 180 top
U13  SRV05-4  [SOT23-6]  123.32 92.99 270 top
U14  SRV05-4  [SOT23-6]  139.33 92.86 270 top
U15  PS2501-1  [4DIP300]  58.34 110.72 90 top
U16  PS2501-1  [4DIP300]  64.11 110.75 90 top
U17  MIC2005-0.5YM6  [SOT23-6]  132.65 110.92 0 top
U18  SRV05-4  [SOT23-6]  142.26 117.82 180 top
U19  PS2501-1  [4DIP300]  25.3 118.31 270 top
U20  B0505S-1W  [B0505S-1W_SIP]  64.79 126.16 180 top
U21  MAX14770EESA+T  [SO8_1P27_4X5]  30.92 128.59 90 top
U22  PS2501-1  [4DIP300]  28.56 110.75 90 top
U23  PS2501-1  [4DIP300]  34.55 110.75 90 top
U24  PS2501-1  [4DIP300]  43.22 118.23 270 top
U25  MAX14770EESA+T  [SO8_1P27_4X5]  49.1 129.41 90 top
U26  PS2501-1  [4DIP300]  46.53 110.67 90 top
U27  PS2501-1  [4DIP300]  52.57 110.75 90 top
U28  SP3232  [SSOP16]  130.8 36.78 0 top
U29  MAX706TESA  [SO8_1P27_4X5]  120.34 21.96 180 top
U30  RT8055GSP  [SO8_1P27_4X5_TAB]  116.54 112.63 0 top
U31  NCP1117ST33T3G  [SOT223]  54.24 91.25 0 top
U32  MCP6002-E/SN  [SO8_1P27_4X5]  49.36 15.81 180 top
V1  MOV-07D561K  [VARISTOR_5_9X5P8_TH]  5.33 81.68 90 top
V2  MOV-07D561K  [VARISTOR_5_9X5P8_TH]  5.2 53.12 90 top
V3  MOV-07D561K  [VARISTOR_5_9X5P8_TH]  5.2 19.86 90 top
V4  MOV-07D221K  [VARISTOR_5_9X5P8_TH]  27.8 145.59 180 top
V5  MOV-07D221K  [VARISTOR_5_9X5P8_TH]  12.87 145.62 180 top
V6  MOV-07D221K  [VARISTOR_5_9X5P8_TH]  57.5 145.86 180 top
V7  MOV-07D221K  [VARISTOR_5_9X5P8_TH]  42.67 145.76 180 top
V8  V30MLA1206  [RC1206]  141.03 142.33 90 top
Y1  50MHz  [OSC4_5P15X3P35MM]  91.46 45.01 0 top
Y2  25MHz  [XTAL2_4_5P2X3P4]  113.33 80.57 180 top

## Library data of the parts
BT1 = BATTERY_SKT_1
C1 C28 C60 C69 C72 = CAP_NP: room: RMII_PHY
C2-C27 C29-C59 C61-C68 C70 C71 C73-C78 C80-C93 C95-C103 C105-C108 C110-C113 C115-C126 = CAP_NP
C104 = CAP_NP: signal model: DEFAULT_CAPACITOR_1e+06pF_2_1
C109 C114 = MOT_CAP: signal model: DEFAULT_CAPACITOR_4.7e+07pF_2_1
CT1 CT2 = CT_2A
D1 D2 = DIODE_SCHTKY
D3-D7 D13-D18 = DIODE_BIDIR_0
D8 D9 D12 = LED
D10 D11 = BTSS-2P_0
DN1 DN2 = ESDA14V2L
F1 = FUSE
J1-J9 J12 J14 J17 = CONN_HDR_2X1
J10 J18 J21 J22 = HDR_2X10
J11 = USB_A
J13 = CON_HDR_1X4
J15 = CONN_HDR_3X1
J16 = CONN_DB9F_MTGTABS
L1-L11 L15-L18 L20-L23 L26 L27 = BEAD_0: room: RMII_PHY
L12 = BEAD_0
L14 = DLW43
L24 = BEAD
L25 = INDUCTOR
P1 P2 = RJ45_LED
P3 = DC POWER JACK
PT1-PT3 = PT_4P
Q1 Q2 = NPN
Q3 Q4 = MOSFET_P
Q5 Q6 = 2N7002
QZ1 = XTAL
R1-R18 R23-R58 R63-R69 R71-R74 R79-R106 R109-R133 R135 R137 R139 R141 R142 R144 R145 R149-R163 = RES
R59-R62 R75-R78 = RES: room: RMII_PHY
R70 R107 R108 R134 R136 R138 R140 R143 R146-R148 = RES: signal model: DEFAULT_RESISTOR_0.001OHM_2_1
SS1-SS4 = SPACER
SW1-SW3 = SW_PB_ESW
T1 T2 = H1102
TP1-TP4 TP8-TP13 TP17-TP20 TP25-TP31 TP34-TP43 TP45-TP49 = Test pad
TP5-TP7 TP21-TP24 TP32 TP33 TP44 TP_GND1-TP_GND8 = TestLoop
TVS1-TVS6 = DIODE_TVS_BIDIR
U1 = K60_LQ_LQFP_0
U2 = DS3231MZ
U3 = 64LV25616AL
U4 = NC7SZ14
U5 = M25P32
U6 = OPAMP_QUAD_14P
U7 = MAX44285
U8 = ADR34XX_SOT23_6P
U9 U10 U13 U14 U18 = SRV05-4
U11 = LAN8720A-QFN24: room: RMII_PHY
U12 = DM9000A_QFP48
U15 U16 U19 U22-U24 U26 U27 = PHOTOCOUPLER_4P
U17 = MIC2015-0.5YM6
U20 = B0505S-1W
U21 U25 = MAX13485
U28 = SP3232E
U29 = ADM706_8P
U30 = RT8011A_16_2
U31 = LD1117AS18
U32 = OPAMP_DUAL_8P_D
V1-V8 = VARISTOR
Y1 = CLKGEN-SM
Y2 = CRYSTAL

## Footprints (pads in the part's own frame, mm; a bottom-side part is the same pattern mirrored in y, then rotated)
4DIP300
  rect 1.499x1.499 hole 0.914: 1(0,0)
  round 1.499 hole 0.914: 2(0,-2.54) 3(7.62,-2.54) 4(7.62,0)
B0505S-1W_SIP
  round 1.524 hole 1.016: 1(-3.81,0) 2(-1.27,0) 3(1.27,0) 4(3.81,0)
BAT_621
  rect 0.61x1.829 smd: 1(-0.75,-1.6) 2(0.75,-1.6)
C035S
  round 0.889 smd: 1(0,0)
CC0603
  rect 0.991x0.813 smd: 1(-0.686,0) 2(0.686,0)
CC0805
  rect 1.295x1.499 smd: 1(-0.965,0) 2(0.965,0)
CC1206
  rect 1.6x1.6 smd: 1(-1.753,0) 2(1.753,0)
CC1210
  rect 1.778x2.845 smd: 1(-1.397,0) 2(1.397,0)
CON3_3P5_11X7MM
  rect 2.007x2.007 hole 1.397: 1(0,0)
  round 2.007 hole 1.397: 2(3.5,0) 3(7,0)
CON4_3P5_14P5X7MM
  rect 2.007x2.007 hole 1.397: 1(0,0)
  round 2.007 hole 1.397: 2(3.5,0) 3(7,0) 4(10.5,0)
CON8_RJ45_LED_JACK
  round 0.254 hole 3.251 unplated: (-9.935,-2.54) (2.765,-2.54)
  rect 1.524x1.524 hole 0.914: 1(0,0)
  round 1.524 hole 0.914: 2(-1.02,1.78) 3(-2.04,0) 4(-3.06,1.78) 5(-4.08,0) 6(-5.1,1.78) 7(-6.12,0) 8(-7.14,1.78)
  round 1.524 hole 1.016: 9(3.29,6.59) 10(1,6.59) 11(-8.14,6.59) 12(-10.43,6.59)
  round 2.54 hole 1.88: S1(-11.785,1.02) S2(4.615,1.02)
CON_DB9S_RA_318
  rect 1.676x1.676 hole 1.016: 1(0,0)
  round 1.676 hole 1.016: 2(0,-2.743) 3(0,-5.486) 4(0,-8.23) 5(0,-10.973) 6(2.845,-1.372) 7(2.845,-4.115) 8(2.845,-6.858) 9(2.845,-9.601)
  round 3.81 hole 3.175: M1(1.422,7.01) M2(1.422,-17.983)
CT_2A
  round 1.524 hole 1.016: 1(-6.25,0) 2(6.25,0)
DO-214AA
  rect 2x2.4 smd: A(2.032,0) C(-2.032,0)
DO-214AA_BIDIR
  rect 1.626x2.184 smd: 1(-2.108,0) 2(2.108,0)
FUSE_3P4X1P8
  rect 0.991x1.803 smd: 1(-1.25,0) 2(1.25,0)
H1102_XFMR16_SM
  rect 1.651x0.762 smd: 1(-4.255,4.445) 2(-4.255,3.175) 3(-4.255,1.905) 4(-4.255,0.635) 5(-4.255,-0.635) 6(-4.255,-1.905) 7(-4.255,-3.175) 8(-4.255,-4.445) 9(4.255,-4.445) 10(4.255,-3.175) 11(4.255,-1.905) 12(4.255,-0.635) 13(4.255,0.635) 14(4.255,1.905) 15(4.255,3.175) 16(4.255,4.445)
HDR102
  rect 1.524x1.524 hole 1.016: 1(0,0)
  round 1.524 hole 1.016: 2(0,-2.54)
HDR210_2MM
  round 1.219 hole 0.813: 1(-9,-1) 2(-9,1) 3(-7,-1) 4(-7,1) 5(-5,-1) 6(-5,1) 7(-3,-1) 8(-3,1) 9(-1,-1) 10(-1,1) 11(1,-1) 12(1,1) 13(3,-1) 14(3,1) 15(5,-1) 16(5,1) 17(7,-1) 18(7,1) 19(9,-1) 20(9,1)
HDR_2X10
  rect 1.676x1.676 hole 1.016: 1(0,0)
  round 1.676 hole 1.016: 2(2.54,0) 3(0,-2.54) 4(2.54,-2.54) 5(0,-5.08) 6(2.54,-5.08) 7(0,-7.62) 8(2.54,-7.62) 9(0,-10.16) 10(2.54,-10.16) 11(0,-12.7) 12(2.54,-12.7) 13(0,-15.24) 14(2.54,-15.24) 15(0,-17.78) 16(2.54,-17.78) 17(0,-20.32) 18(2.54,-20.32) 19(0,-22.86) 20(2.54,-22.86)
IND2_6P3X6P3
  rect 1.6x5.7 smd: 1(-2.3,0) 2(2.3,0)
IND4_CHOKE_0805
  rect 0.914x0.406 smd: 1(-0.85,-0.4) 2(0.85,-0.4) 3(0.85,0.4) 4(-0.85,0.4)
IND_0603
  rect 0.991x0.813 smd: 1(-0.69,0) 2(0.69,0)
IND_0805
  rect 1.295x1.499 smd: 1(-0.978,0) 2(0.978,0)
LED_0603
  rect 0.838x0.787 smd: A(-0.775,0) C(0.775,0)
LQFP48
  rect 1.524x0.305 smd: 1(-4.204,2.752) 2(-4.204,2.252) 3(-4.204,1.751) 4(-4.204,1.251) 5(-4.204,0.751) 6(-4.204,0.25) 7(-4.204,-0.25) 8(-4.204,-0.751) 9(-4.204,-1.251) 10(-4.204,-1.751) 11(-4.204,-2.252) 12(-4.204,-2.752) 25(4.204,-2.752) 26(4.204,-2.252) 27(4.204,-1.751) 28(4.204,-1.251) 29(4.204,-0.751) 30(4.204,-0.25) 31(4.204,0.25) 32(4.204,0.751) 33(4.204,1.251) 34(4.204,1.751) 35(4.204,2.252) 36(4.204,2.752)
  rect 0.305x1.524 smd: 13(-2.752,-4.204) 14(-2.252,-4.204) 15(-1.751,-4.204) 16(-1.251,-4.204) 17(-0.751,-4.204) 18(-0.25,-4.204) 19(0.25,-4.204) 20(0.751,-4.204) 21(1.251,-4.204) 22(1.751,-4.204) 23(2.252,-4.204) 24(2.752,-4.204) 37(2.752,4.204) 38(2.252,4.204) 39(1.751,4.204) 40(1.251,4.204) 41(0.751,4.204) 42(0.25,4.204) 43(-0.25,4.204) 44(-0.751,4.204) 45(-1.251,4.204) 46(-1.751,4.204) 47(-2.252,4.204) 48(-2.752,4.204)
LQFP144_0P5_20X20MM
  rect 1.422x0.279 smd: 1(-10.7,8.75) 2(-10.7,8.25) 3(-10.7,7.75) 4(-10.7,7.25) 5(-10.7,6.75) 6(-10.7,6.25) 7(-10.7,5.75) 8(-10.7,5.25) 9(-10.7,4.75) 10(-10.7,4.25) 11(-10.7,3.75) 12(-10.7,3.25) 13(-10.7,2.75) 14(-10.7,2.25) 15(-10.7,1.75) 16(-10.7,1.25) 17(-10.7,0.75) 18(-10.7,0.25) 19(-10.7,-0.25) 20(-10.7,-0.75) 21(-10.7,-1.25) 22(-10.7,-1.75) 23(-10.7,-2.25) 24(-10.7,-2.75) 25(-10.7,-3.25) 26(-10.7,-3.75) 27(-10.7,-4.25) 28(-10.7,-4.75) 29(-10.7,-5.25) 30(-10.7,-5.75) 31(-10.7,-6.25) 32(-10.7,-6.75) 33(-10.7,-7.25) 34(-10.7,-7.75) 35(-10.7,-8.25) 36(-10.7,-8.75) 73(10.7,-8.75) 74(10.7,-8.25) 75(10.7,-7.75) 76(10.7,-7.25) 77(10.7,-6.75) 78(10.7,-6.25) 79(10.7,-5.75) 80(10.7,-5.25) 81(10.7,-4.75) 82(10.7,-4.25) 83(10.7,-3.75) 84(10.7,-3.25) 85(10.7,-2.75) 86(10.7,-2.25) 87(10.7,-1.75) 88(10.7,-1.25) 89(10.7,-0.75) 90(10.7,-0.25) 91(10.7,0.25) 92(10.7,0.75) 93(10.7,1.25) 94(10.7,1.75) 95(10.7,2.25) 96(10.7,2.75) 97(10.7,3.25) 98(10.7,3.75) 99(10.7,4.25) 100(10.7,4.75) 101(10.7,5.25) 102(10.7,5.75) 103(10.7,6.25) 104(10.7,6.75) 105(10.7,7.25) 106(10.7,7.75) 107(10.7,8.25) 108(10.7,8.75)
  rect 0.279x1.422 smd: 37(-8.75,-10.7) 38(-8.25,-10.7) 39(-7.75,-10.7) 40(-7.25,-10.7) 41(-6.75,-10.7) 42(-6.25,-10.7) 43(-5.75,-10.7) 44(-5.25,-10.7) 45(-4.75,-10.7) 46(-4.25,-10.7) 47(-3.75,-10.7) 48(-3.25,-10.7) 49(-2.75,-10.7) 50(-2.25,-10.7) 51(-1.75,-10.7) 52(-1.25,-10.7) 53(-0.75,-10.7) 54(-0.25,-10.7) 55(0.25,-10.7) 56(0.75,-10.7) 57(1.25,-10.7) 58(1.75,-10.7) 59(2.25,-10.7) 60(2.75,-10.7) 61(3.25,-10.7) 62(3.75,-10.7) 63(4.25,-10.7) 64(4.75,-10.7) 65(5.25,-10.7) 66(5.75,-10.7) 67(6.25,-10.7) 68(6.75,-10.7) 69(7.25,-10.7) 70(7.75,-10.7) 71(8.25,-10.7) 72(8.75,-10.7) 109(8.75,10.7) 110(8.25,10.7) 111(7.75,10.7) 112(7.25,10.7) 113(6.75,10.7) 114(6.25,10.7) 115(5.75,10.7) 116(5.25,10.7) 117(4.75,10.7) 118(4.25,10.7) 119(3.75,10.7) 120(3.25,10.7) 121(2.75,10.7) 122(2.25,10.7) 123(1.75,10.7) 124(1.25,10.7) 125(0.75,10.7) 126(0.25,10.7) 127(-0.25,10.7) 128(-0.75,10.7) 129(-1.25,10.7) 130(-1.75,10.7) 131(-2.25,10.7) 132(-2.75,10.7) 133(-3.25,10.7) 134(-3.75,10.7) 135(-4.25,10.7) 136(-4.75,10.7) 137(-5.25,10.7) 138(-5.75,10.7) 139(-6.25,10.7) 140(-6.75,10.7) 141(-7.25,10.7) 142(-7.75,10.7) 143(-8.25,10.7) 144(-8.75,10.7)
MSOP08_0P65_3P2X3P2
  rect 1.346x0.432 smd: 1(-2.264,0.975) 2(-2.264,0.325) 3(-2.264,-0.325) 4(-2.264,-0.975) 5(2.264,-0.975) 6(2.264,-0.325) 7(2.264,0.325) 8(2.264,0.975)
OSC4_5P15X3P35MM
  rect 1.702x1.524 smd: 1(-1.27,-1.1) 2(1.27,-1.1) 3(1.27,1.1) 4(-1.27,1.1)
PJ-202B
  rect 1.651x5.74 hole 1.016x4.521: 1(0,0)
  rect 1.651x4.953 hole 1.016x4.013: 2(6,0)
  rect 4.953x1.651 hole 4.013x1.016: 3(3,4.7)
PT_4P
  round 1.524 hole 1.016: 1(-5,-6.4) 2(-5,6.4) 3(5,-6.4) 4(5,6.4)
QFN24_4X4MM_SLUG
  oval 0.279x0.711 smd: 1(-1.25,-1.956) 2(-0.75,-1.956) 3(-0.25,-1.956) 4(0.25,-1.956) 5(0.75,-1.956) 6(1.25,-1.956) 13(1.25,1.956) 14(0.75,1.956) 15(0.25,1.956) 16(-0.25,1.956) 17(-0.75,1.956) 18(-1.25,1.956)
  oval 0.711x0.279 smd: 7(1.956,-1.25) 8(1.956,-0.75) 9(1.956,-0.25) 10(1.956,0.25) 11(1.956,0.75) 12(1.956,1.25) 19(-1.956,1.25) 20(-1.956,0.75) 21(-1.956,0.25) 22(-1.956,-0.25) 23(-1.956,-0.75) 24(-1.956,-1.25)
  rect 2.616x2.616 smd: 25(0,0)
RC0603
  rect 0.991x0.813 smd: 1(-0.8,0) 2(0.8,0)
RC0805
  rect 1.295x1.499 smd: 1(-0.965,0) 2(0.965,0)
RC1206
  rect 1.6x1.6 smd: 1(-1.753,0) 2(1.753,0)
RC2010
  rect 1.6x2.997 smd: 1(-2.438,0) 2(2.438,0)
RC_MELF_0204
  rect 1.778x1.778 smd: 1(-1.625,0) 2(1.625,0)
RES_TH
  round 1.524 hole 1.016: 1(-14.15,0) 2(14.15,0)
SO8_1P27_4X5
  rect 1.6x0.61 smd: 1(-2.7,1.905) 2(-2.7,0.635) 3(-2.7,-0.635) 4(-2.7,-1.905) 5(2.7,-1.905) 6(2.7,-0.635) 7(2.7,0.635) 8(2.7,1.905)
SO8_1P27_4X5_TAB
  rect 1.6x0.61 smd: 1(-2.7,1.905) 2(-2.7,0.635) 3(-2.7,-0.635) 4(-2.7,-1.905) 5(2.7,-1.905) 6(2.7,-0.635) 7(2.7,0.635) 8(2.7,1.905)
  rect 2.413x3.099 smd: 9(0,0)
SO8WST
  rect 2.032x0.61 smd: 1(-3.81,1.905) 2(-3.81,0.635) 3(-3.81,-0.635) 4(-3.81,-1.905) 5(3.81,-1.905) 6(3.81,-0.635) 7(3.81,0.635) 8(3.81,1.905)
SOD323
  rect 0.889x1.219 smd: A(0,1.27) C(0,-1.27)
SOIC14_1P27_4X8
  rect 1.448x0.61 smd: 1(-2.726,3.81) 2(-2.726,2.54) 3(-2.726,1.27) 4(-2.726,0) 5(-2.726,-1.27) 6(-2.726,-2.54) 7(-2.726,-3.81) 8(2.726,-3.81) 9(2.726,-2.54) 10(2.726,-1.27) 11(2.726,0) 12(2.726,1.27) 13(2.726,2.54) 14(2.726,3.81)
SOT23-6
  rect 0.61x1.118 smd: 1(-0.95,-1.321) 2(0,-1.321) 3(0.95,-1.321) 4(0.95,1.321) 5(0,1.321) 6(-0.95,1.321)
SOT223
  rect 1.194x2.21 smd: 1(-2.3,-3.1) 2(0,-3.1) 3(2.3,-3.1)
  rect 3.734x2.21 smd: 4(0,3.1)
SOT-23
  rect 1.016x1.397 smd: 1(-0.95,-1.1) 2(0.95,-1.1) 3(0,1.1)
SOT-23-5
  rect 0.686x0.991 smd: 1(-0.953,-1.295) 2(0,-1.295) 3(0.953,-1.295) 4(0.953,1.295) 5(-0.953,1.295)
SPACER_139T
  round 5.588 hole 3.531: 1(0,0)
SSOP16
  rect 2.032x0.406 smd: 1(-3.48,2.276) 2(-3.48,1.626) 3(-3.48,0.975) 4(-3.48,0.325) 5(-3.48,-0.325) 6(-3.48,-0.975) 7(-3.48,-1.626) 8(-3.48,-2.276) 9(3.48,-2.276) 10(3.48,-1.626) 11(3.48,-0.975) 12(3.48,-0.325) 13(3.48,0.325) 14(3.48,0.975) 15(3.48,1.626) 16(3.48,2.276)
SW4_PB_ESW_SM_P177
  rect 1.397x2.794 smd: 1(2.248,4.547) 2(2.248,-4.547) 3(-2.248,4.547) 4(-2.248,-4.547)
TP_TH_063
  round 2.311 hole 1.6: 1(0,0)
TPAD_040
  round 1.016 smd: 1(0,0)
TSOP44_T2
  rect 1.778x0.508 smd: 1(-5.588,8.395) 2(-5.588,7.595) 3(-5.588,6.795) 4(-5.588,5.994) 5(-5.588,5.194) 6(-5.588,4.394) 7(-5.588,3.594) 8(-5.588,2.794) 9(-5.588,1.994) 10(-5.588,1.194) 11(-5.588,0.394) 12(-5.588,-0.394) 13(-5.588,-1.194) 14(-5.588,-1.994) 15(-5.588,-2.794) 16(-5.588,-3.594) 17(-5.588,-4.394) 18(-5.588,-5.194) 19(-5.588,-5.994) 20(-5.588,-6.795) 21(-5.588,-7.595) 22(-5.588,-8.395) 23(5.588,-8.395) 24(5.588,-7.595) 25(5.588,-6.795) 26(5.588,-5.994) 27(5.588,-5.194) 28(5.588,-4.394) 29(5.588,-3.594) 30(5.588,-2.794) 31(5.588,-1.994) 32(5.588,-1.194) 33(5.588,-0.394) 34(5.588,0.394) 35(5.588,1.194) 36(5.588,1.994) 37(5.588,2.794) 38(5.588,3.594) 39(5.588,4.394) 40(5.588,5.194) 41(5.588,5.994) 42(5.588,6.795) 43(5.588,7.595) 44(5.588,8.395)
unnamed#2
  round 1.016 smd: 1(0,0)
USB_A
  rect 1.676x1.676 hole 1.016: A1(0,0)
  round 1.676 hole 1.016: A2(2.499,0) A3(4.501,0) A4(7,0)
  round 4.013 hole 2.413: S1(-3.071,-2.71) S2(10.071,-2.71)
VARISTOR_5_9X5P8_TH
  rect 1.88x1.88 hole 1.118: 1(0,0)
  round 1.88 hole 1.118: 2(5,-4.35)
XTAL2-3P2X1P5-SM
  rect 1.092x1.905 smd: 1(-1.25,0) 2(1.25,0)
XTAL2_4_5P2X3P4
  rect 2.007x2.413 smd: 1(-2,0) 2(2,0)

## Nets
5V_DC_JACK: F1.1 P3.1(PIN) V8.1
5V_IN: C103.1 C104.1 C105.1 F1.2 L24.1 R157.2 TVS6.2(A2)
AGND: C85.2 C87.1 C88.2 J13.3 J15.2 L18.2 R107.2 R108.2 R117.1 R127.1 TVS2.1(A1) TVS3.2(A2) TVS4.1(A1) TVS5.2(A2) U20.3(0) U21.5(GND) U22.3(EMITTER) U23.3(EMITTER) U25.5(GND) U26.3(EMITTER) U27.3(EMITTER) V4.2 V5.1 V6.2 V7.1
GND: BT1.1(POS1) C1.2 C2.2 C3.2 C4.2 C5.2 C6.2 C7.2 C8.2 C9.2 C10.2 C17.2 C18.2 C19.2 C20.2 C21.2 C22.2 C23.2 C24.2 C25.2 C26.2 C27.2 C28.2 C29.2 C30.2 C31.2 C60.2 C61.2 C62.2 C63.2 C64.2 C66.1 C67.2 C68.2 C69.2 C70.2 C71.2 C72.2 C73.2 C74.2 C75.2 C77.2 C78.2 C80.2 C81.2 C82.2 C84.2 C86.1 C89.2 C90.2 C91.1 C95.2 C96.2 C97.2 C98.2 C99.2 C101.2 C103.2 C104.2 C105.2 C106.2 C107.2 C108.2 C109.2 C110.2 C111.2 C112.2 C113.2 C114.2 C115.2 C116.2 C125.2 C126.2 D10.C(2) D11.C(2) D12.C(CATHODE) DN1.2 DN2.2 J10.2 J11.A4(GND) J16.5 J18.4 J18.6 J18.8 J18.10 J18.12 J18.14 J18.16 J18.18 J18.20 J21.7 J21.9 J21.11 J22.5 J22.7 L2.2 L18.1 P3.2 P3.3 Q1.2(EMITTER) Q2.2(EMITTER) Q5.2(SOURCE) Q6.2(SOURCE) R26.1 R67.2 R72.1 R73.2 R74.1 R88.1 R94.2 R97.2 R155.2 R156.2 R159.1 R161.1 SW1.1(A1) SW1.2(A2) SW2.1(A1) SW2.2(A2) SW3.1(A1) SW3.2(A2) TP_GND1.1(PIN1) TP_GND2.1(PIN1) TP_GND3.1(PIN1) TP_GND4.1(PIN1) TP_GND5.1(PIN1) TP_GND6.1(PIN1) TP_GND7.1(PIN1) TP_GND8.1(PIN1) TVS6.1(A1) U1.6(VSS1) U1.17(VSS2) U1.18(VSSUSB) U1.44(VSS3) U1.57(VSS4) U1.71(VSS5) U1.93(VSS6) U1.107(VSS7) U1.121(VSS8) U1.134(VSS9) U2.5(GND) U3.12(GND1) U3.34(GND2) U4.3(GND) U5.4(VSS) U9.2(GND) U10.2(GND) U11.25(VSS) U12.5(RXGND1) U12.6(TXGND) U12.15(GND1) U12.33(GND2) U12.41(TEST) U12.45(GND3) U12.47(RXGND2) U12.48(BGGND) U13.2(GND) U14.2(GND) U17.2(GND) U18.2(GND) U19.3(EMITTER) U20.1(GND) U24.3(EMITTER) U28.15(GND) U29.3(GND) U29.4(PFI) U30.2(GND) U30.4(PGND) U30.9(PAD) U31.1(GND) V8.2 Y1.2(GND)
GND_EARTH: C65.2 C66.2 C76.2 J11.S1(SGND1) J11.S2(SGND2) J16.M1 J16.M2 P1.S1 P1.S2 P2.S1 P2.S2 R72.2 SS2.1(NC_1) SS3.1(NC_1) SS4.1(NC_1)
GNDA: C11.2 C12.2 C13.2 C14.2 C15.2 C16.2 C32.2 C33.2 C34.2 C35.2 C36.2 C38.1 C39.2 C40.1 C42.2 C43.2 C45.1 C47.2 C48.2 C49.2 C50.2 C53.1 C54.1 C55.2 C56.2 C57.2 C58.2 C59.2 C117.2 C118.2 C119.2 C120.2 C121.2 C122.2 C124.2 D3.C(C2) D4.C(C2) D5.C(C2) D6.C(C2) D7.C(C2) D13.C(C2) D14.C(C2) D15.C(C2) D16.C(C2) D17.C(C2) D18.C(C2) J5.2 L2.1 R47.2 R163.2 TVS1.1(A1) U1.33(VREFL) U1.34(VSSA) U6.11(VEE) U7.5(GND) U8.1(GND_FORCE) U8.2(GND_SENSE) U32.4(VSS)
GPRS_3V3/5V: C101.1 C102.1 J22.1 J22.3 Q4.3(DRAIN)
P3V3_LICELL: BT1.2(POS2) C27.1 D2.A R17.1
VBAT: C23.1 C24.1 C25.1 D1.C D2.C R17.2 U1.42(VBAT) U2.6(VBAT)
VCC_3V3: C114.1 C115.1 C116.1 L4.2 TP33.1(PIN1) U31.2(VOUT) U31.4(TAB)
VDD_3V3: C1.1 C2.1 C3.1 C4.1 C5.1 C6.1 C7.1 C8.1 C9.1 C10.1 C22.1 C26.1 C28.1 C29.1 C30.1 C31.1 C62.1 C69.1 C70.1 C71.1 C90.1 C96.1 C109.1 C110.1 D1.A D8.A(ANODE) D9.A(ANODE) J10.1 J18.1 L3.2 L11.1 L20.2 L21.2 L25.2 P2.10(LED2+) R1.1 R5.1 R6.1 R7.1 R8.1 R16.1 R23.2 R24.2 R25.2 R56.2 R57.2 R58.2 R71.1 R79.2 R80.2 R81.2 R82.2 R83.2 R109.1 R110.1 R111.1 R112.2 R120.2 R142.1 R144.1 R145.1 R158.2 TP32.1(PIN1) U1.5(VDD1) U1.16(VDD2) U1.43(VDD3) U1.56(VDD4) U1.70(VDD5) U1.94(VDD6) U1.108(VDD7) U1.122(VDD8) U1.135(VDD9) U2.2(VCC) U3.11(VDD1) U3.33(VDD2) U4.5(VCC) U5.8(VCC) U11.9(VDDIO) U12.23(VDD1) U12.30(VDD2) U12.42(VDD3) U15.1(ANODE) U16.1(ANODE) U22.1(ANODE) U23.1(ANODE) U26.1(ANODE) U27.1(ANODE) U28.16(VCC) U29.2(VCC) Y1.4(VDD)
VDD_5V: C19.1 C82.1 C83.2 C86.2 C106.1 C107.1 C108.1 C112.1 C113.1 L16.1 L22.2 L23.2 L24.2 R3.2 U17.1(VIN) U20.2(VIN) U30.5(PVDD) U30.6(VDD) U31.3(VIN)
VDDA_2V5: C72.1 C73.1 C74.1 C75.1 T2.2 T2.7 U12.2(RXVDD25) U12.9(TXVDD25) U13.5(VCC)
VDDA_3V3: C15.1 C16.1 C32.1 C33.1 C56.1 C57.1 C117.1 C118.1 L1.2 L3.1 L4.1 U1.31(VDDA) U6.4(VCC) U7.8(VDD) U8.3(ENABLE) U8.4(VIN) U32.8(VDD)
VDDCR_1.2V: C67.1 C68.1 U11.6(VDDCR)
WIFI/LCD_3V3/5V: C98.1 C99.1 C100.1 J21.1 J21.3 J21.5 Q3.3(DRAIN)
ADC_S1: TP4.1(PIN1) U1.80(PTA29/ADC2_SE12/ULPI_DATA7/MII0)
ADC_S2: TP3.1(PIN1) U1.79(PTA28/ADC2_SE13/ULPI_DATA6/MII0)
ADC_S3: TP2.1(PIN1) U1.78(PTA27/ADC2_SE14/ULPI_DATA5/MII0)
ADC_S4: TP1.1(PIN1) U1.77(PTA26/ADC2_SE15/ULPI_DATA4/MII0)
DC_A1_OUT: C55.1 R55.2 U1.59(PTA7/ADC0_SE10/ULPI_DIR/FTM0_CH)
DC_IN: J6.1 R48.1 U7.1(RS1+)
DC_OUT: J6.2 R48.2 U7.2(RS1-)
DC_V1_IN: C46.1 J5.1 R45.1 TVS1.2(A2)
DC_V1_OUT: C48.1 R46.2 U1.60(PTA8/ADC0_SE11/ULPI_NXT/FTM1_CH)
DEBUG_RX: R138.1 U1.51(PTA1/TSI0_CH2/UART0_RX/FTM0_CH6)
DEBUG_TX: R134.1 U1.52(PTA2/TSI0_CH3/UART0_TX/FTM0_CH7)
DM9000_INT#: R95.2 U1.137(PTD8/I2C0_SCL/UART5_RX/FB_A16/N)
DM9000_WAKE: R91.1 U1.73(PTA19/XTAL/FTM1_FLT0/FTM_CLKIN1)
DM_INT: R83.1 R95.1 U12.34(INT)
DM_LED1: P2.9(LED2-) U12.39(LED1)
DM_LED2: P2.12(LED1+) U12.38(LED2)
EECLK: R80.1 U12.20(EECLK)
EECS: R79.1 U12.21(EECS)
ENET1_RX+: R59.2 T1.6 U9.3(I/O3) U11.23(RXP)
ENET1_RX-: R60.2 T1.8 U9.4(I/O4) U11.22(RXN)
ENET1_TX+: R61.2 T1.1 U9.1(I/O1) U11.21(TXP)
ENET1_TX-: R62.2 T1.3 U9.6(I/O6) U11.20(TXN)
ENET2_RX+: R77.2 T2.6 U12.3(RX+) U13.3(I/O3)
ENET2_RX-: R78.2 T2.8 U12.4(RX-) U13.4(I/O4)
ENET2_TX+: R75.2 T2.1 U12.7(TX+) U13.1(I/O1)
ENET2_TX-: R76.2 T2.3 U12.8(TX-) U13.6(I/O6)
ENET_3V3A: C60.1 C61.1 C63.1 C64.1 L11.2 P1.10(LED2+) R59.1 R60.1 R61.1 R62.1 R70.2 T1.2 T1.7 U9.5(VCC) U11.1(VDD2A) U11.19(VDD1A)
ETH1_RXN: P1.6 T1.9 U10.3(I/O3)
ETH1_RXP: P1.3 T1.11 U10.4(I/O4)
ETH1_TXN: P1.2 T1.14 U10.6(I/O6)
ETH1_TXP: P1.1 T1.16 U10.1(I/O1)
ETH2_RXN: P2.6 T2.9 U14.3(I/O3)
ETH2_RXP: P2.3 T2.11 U14.4(I/O4)
ETH2_TXN: P2.2 T2.14 U14.6(I/O6)
ETH2_TXP: P2.1 T2.16 U14.1(I/O1)
EXT_5V: J13.1 L17.1
EXTAL: R18.2 U1.72(PTA18/EXTAL/FTM0_FLT2/FTM_CLKIN) U11.5(XTAL1/CLKIN)
EZP_CS: R1.2 U1.54(PTA4/TSI0_CH5/FTM0_CH1/N\M\I\/E)
FB_AD0: U1.133(PTD6/ADC0_SE7B/SPI0_PCS3/UART0_) U3.40(U\B\) U4.2(A)
FB_AD0_N: U3.39(L\B\) U4.4(Y)
FB_AD1: U1.132(PTD5/ADC0_SE6B/SPI0_PCS2/U\A\R\) U3.1(A0) U12.32(CMD)
FB_AD2: U1.131(PTD4/SPI0_PCS1/U\A\R\T\0\_\R\T\) U3.2(A1)
FB_AD3: U1.130(PTD3/SPI0_SIN/UART2_TX/FTM3_CH3) U3.3(A2)
FB_AD4: U1.129(PTD2/SPI0_SOUT/UART2_RX/FTM3_CH) U3.4(A3)
FB_AD5: U1.115(PTC10/ADC1_SE6B/I2C1_SCL/FTM3_C) U3.5(A4)
FB_AD6: U1.114(PTC9/ADC1_SE5B/CMP0_IN3/FTM3_CH) U3.18(A5)
FB_AD7: U1.113(PTC8/ADC1_SE4B/CMP0_IN2/FTM3_CH) U3.19(A6)
FB_AD8: U1.112(PTC7/CMP0_IN1/SPI0_SIN/USB_SOF_) U3.20(A7)
FB_AD9: U1.111(PTC6/CMP0_IN0/SPI0_SOUT/PDB0_EX) U3.21(A8)
FB_AD10: U1.110(PTC5/SPI0_SCK/LPTMR0_ALT2/FB_AD) U3.22(A9)
FB_AD11: U1.109(PTC4/SPI0_PCS0/UART1_TX/FTM0_CH) U3.23(A10)
FB_AD12: U1.105(PTC2/ADC0_SE4B/TSI0_CH15/SPI0_P) U3.24(A11)
FB_AD13: U1.104(PTC1/ADC0_SE15/TSI0_CH14/SPI0_P) U3.25(A12)
FB_AD14: U1.103(PTC0/ADC0_SE14/TSI0_CH13/SPI0_P) U3.26(A13)
FB_AD15: U1.97(PTB18/TSI0_CH11/CAN0_TX/FTM2_CH) U3.27(A14)
FB_AD16: U1.96(PTB17/TSI0_CH10/SPI1_SIN/UART0_) U3.42(A15)
FB_AD17: U1.95(PTB16/TSI0_CH9/SPI1_SOUT/UART0_) U3.43(A16)
FB_AD18: U1.92(PTB11/ADC1_SE15/SPI1_SCK/UART3_) U3.44(A17)
FB_AD24: U1.120(PTC15/UART4_TX/FB_AD24) U3.7(I/O0) U3.29(I/O8) U12.18(SD0)
FB_AD25: U1.119(PTC14/UART4_RX/FB_AD25) U3.8(I/O1) U3.30(I/O9) U12.17(SD1)
FB_AD26: U1.118(PTC13/U\A\R\T\4\_\C\T\S\/FB_AD2) U3.9(I/O2) U3.31(I/O10) U12.16(SD2)
FB_AD27: U1.117(PTC12/U\A\R\T\4\_\R\T\S\/FB_AD2) U3.10(I/O3) U3.32(I/O11) U12.14(SD3)
FB_AD28: U1.102(PTB23/SPI2_SIN/SPI0_PCS5/FB_AD2) U3.13(I/O4) U3.35(I/O12) U12.13(SD4)
FB_AD29: U1.101(PTB22/SPI2_SOUT/FB_AD29/NFC_DAT) U3.14(I/O5) U3.36(I/O13) U12.12(SD5)
FB_AD30: U1.100(PTB21/ADC2_SE5A/SPI2_SCK/FB_AD3) U3.15(I/O6) U3.37(I/O14) U12.11(SD6)
FB_AD31: U1.99(PTB20/ADC2_SE4A/SPI2_PCS0/FB_AD) U3.16(I/O7) U3.38(I/O15) U12.10(SD7)
FB_CS0_N: U1.128(PTD1/ADC0_SE5B/SPI0_SCK/U\A\R\T) U3.6(C\E\)
FB_CS1_N: U1.127(PTD0/SPI0_PCS0/U\A\R\T\2\_\R\T\) U12.37(C\S\)
FB_OE_N: U1.98(PTB19/TSI0_CH12/CAN0_RX/FTM2_CH) U3.41(O\E\) U12.35(I\O\R\)
FB_RW_N: U1.116(PTC11/ADC1_SE7B/I2C1_SDA/FTM3_C) U3.17(W\E\) U12.36(I\O\W\)
GP6: R82.1 TP13.1(PIN1) U12.25(SD13/GP6)
GPIO_1: J10.3 U1.87(PTB6/ADC1_SE12/FB_AD23)
GPIO_2: J10.4 U1.88(PTB7/ADC1_SE13/FB_AD22)
GPIO_3: J10.5 U1.76(PTA25/CMP3_IN5/ULPI_DATA3/MII0_)
GPIO_4: J10.6 U1.47(PTE26/ADC3_SE5B/ENET_1588_CLKIN)
GPIO_5: J10.7 U1.48(PTE27/ADC3_SE4B/U\A\R\T\4\_\R\T)
GPIO_6: J10.8 U1.49(PTE28/ADC3_SE7A)
GPIO_7: J10.9 U1.58(PTA6/ADC3_SE6A/ULPI_CLK/FTM0_CH)
GPIO_8: J10.10 U1.61(PTA9/ADC3_SE5A/ULPI_STP/FTM1_CH)
GPIO_9: J10.11 U1.62(PTA10/ADC3_SE4A/ULPI_DATA0/FTM2)
GPIO_10: J10.12 U1.63(PTA11/ADC3_SE15/ULPI_DATA1/FTM2)
GPIO_IN_1: R109.2 SW1.3(B1) SW1.4(B2) U1.85(PTB4/ADC1_SE10/ENET0_1588_TMR2/)
GPIO_IN_2: R110.2 SW2.3(B1) SW2.4(B2) U1.86(PTB5/ADC1_SE11/ENET0_1588_TMR3/)
GPIO_OUT_1: R101.2 U1.89(PTB8/U\A\R\T\3\_\R\T\S\/FB_AD21)
GPIO_OUT_2: R102.2 U1.90(PTB9/SPI1_PCS1/U\A\R\T\3\_\C\T\)
GPIO_OUT_3: R106.2 U1.91(PTB10/ADC1_SE14/SPI1_PCS0/UART3)
GPIO_OUT_4: R105.2 U1.138(PTD9/I2C0_SDA/UART5_TX/FB_A17/N)
GPRS_CTS: J22.6 U1.126(PTC19/U\A\R\T\3\_\C\T\S\/ENET0_)
GPRS_DCD: J22.10 U1.141(PTD12/SPI2_SCK/FTM3_FLT0/SDHC0_)
GPRS_DTR: J22.9 U1.140(PTD11/SPI2_PCS0/U\A\R\T\5\_\C\T)
GPRS_PWR_CNTL: R148.2 R154.2 U1.144(PTD15/SPI2_PCS1/SDHC0_D7/FB_A23)
GPRS_RI: J22.12 U1.142(PTD13/SPI2_SOUT/SDHC0_D5/FB_A21)
GPRS_RST: J22.14 U1.143(PTD14/SPI2_SIN/SDHC0_D6/FB_A22)
GPRS_RTS: J22.8 U1.125(PTC18/U\A\R\T\3\_\R\T\S\/ENET0_)
GPRS_RX: J22.4 U1.124(PTC17/CAN1_TX/UART3_TX/ENET0_15)
GPRS_TX: J22.2 U1.123(PTC16/CAN1_RX/UART3_RX/ENET0_15)
HOSTUSB_C_D_N: J11.A2(DATA+) L14.2 U18.6(I/O6)
HOSTUSB_C_D_P: J11.A3(DATA-) L14.3 U18.1(I/O1)
I1A_IN: CT1.1 R28.1 U6.2(VINA-)
I1A_OUT: C34.1 R27.2 U1.25(ADC3_DP0/ADC2_DP3/ADC1_DP1)
I2A_N: C37.2 C40.2 R34.2 U1.24(ADC2_DM0/ADC3_DM3/ADC0_DM1)
I2A_P: C36.1 C37.1 R29.2 U1.23(ADC2_DP0/ADC3_DP3/ADC0_DP1)
I2C_SCL: R6.2 R14.2 TP6.1(PIN1) U1.83(PTB2/ADC0_SE12/TSI0_CH7/I2C0_SC)
I2C_SDA: R5.2 R15.2 TP5.1(PIN1) U1.84(PTB3/ADC0_SE13/TSI0_CH8/I2C0_SD)
L_XIN: R96.2 U12.44(X1)
L_XOUT: C78.1 U12.43(X2) Y2.2
LED3: R90.2 U12.24(SD14/LED3)
MODE0: R56.1 R63.2 U11.8(RXD0/MODE0)
MODE1: R57.1 R64.2 U11.7(RXD1/MODE1)
NORFLASH_WP: R23.1 R26.2 U5.3(W\/VPP)
PHY_INT_B: R71.2 U11.14(IN\T\/REFCLKO)
PHY_LED1: P1.12(LED1+) U11.3(LED1/REGOFF)
PHY_LED2: R68.2 U11.2(LED2/IN\T\S\E\L\)
PHY_RST_B: R69.2 U11.15(R\S\T\)
PWRST#: R98.2 U12.40(P\W\R\S\T\)
RBIAS: R73.1 U11.24(RBIAS)
RESET_B: C97.1 J18.15 R11.2 R69.1 R98.1 R144.2 R146.2
RMII0_CRS_DV: R58.1 U1.66(PTA14/CMP3_IN0/SPI0_PCS0/UART0_) U11.11(CRS_DV/MODE2)
RMII0_MDC: R7.2 U1.82(PTB1/ADC0/1/2/3_SE9/TSI0_CH6/I2) U11.13(MDC)
RMII0_MDIO: R8.2 U1.81(PTB0/ADC0/1/2/3_SE8/TSI0_WU/I2C) U11.12(MDIO)
RMII0_RXD0: R63.1 U1.65(PTA13/CAN0_RX/FTM1_CH1/RMII0_RX)
RMII0_RXD1: R64.1 U1.64(PTA12/CAN0_TX/FTM1_CH0/RMII0_RX)
RMII0_RXER: R70.1 R74.2 U1.55(PTA5/USB_CLKIN/FTM0_CH2/RMII0_R) U11.10(RXER/PHYAD0)
RMII0_TXD0: R2.1 U11.17(TXD0)
RMII0_TXD1: R4.1 U11.18(TXD1)
RMII0_TXEN: U1.67(PTA15/CMP3_IN1/SPI0_SCK/UART0_R) U11.16(TXEN)
RS485_5V: C85.1 C87.2 C88.1 L15.2 L16.2 L17.2 R103.1 R104.1 R114.1 R116.1 R118.1 R123.1 R126.1 R130.1 U19.1(ANODE) U21.8(VCC) U24.1(ANODE) U25.8(VCC)
RS485I_A: J12.2 R116.2 R122.1 TVS2.2(A2) U21.6(A)
RS485I_B: R117.2 R124.2 R128.1 TVS3.1(A1) U21.7(B)
RS485I_DIR: R115.2 U1.14(PTE11/ADC3_SE16/U\A\R\T\5\_\R\T)
RS485I_RX: R112.1 U1.46(PTE25/ADC0_SE18/XTAL1/CAN1_RX/U) U19.4(COLLECTOR)
RS485I_TX: R119.2 U1.45(PTE24/ADC0_SE17/EXTAL1/CAN1_TX/)
RS485IA: J13.2 R122.2 V4.1
RS485IB: J13.4 R128.2 V5.2
RS485II_A: J14.2 R126.2 R129.1 TVS4.2(A2) U25.6(A)
RS485II_B: R127.2 R132.2 R133.1 TVS5.1(A1) U25.7(B)
RS485II_DIR: R125.2 U1.13(PTE10/U\A\R\T\5\_\C\T\S\/FTM3_C)
RS485II_RX: R120.1 U1.12(PTE9/ADC2_SE17/UART5_RX/FTM3_CH) U24.4(COLLECTOR)
RS485II_TX: R131.2 U1.11(PTE8/ADC2_SE16/UART5_TX/FTM3_CH)
RS485IIA: J15.1 R129.2 V6.1
RS485IIB: J15.3 R133.2 V7.2
RTC_XTALI: C21.1 QZ1.2 R12.2
RTC_XTALO: C20.1 QZ1.1 U1.40(XTAL32)
RX232_RX1: R141.2 TP24.1(PIN1)
RX232_TX1: R137.2 TP23.1(PIN1)
SPI1_PCS0: R24.1 U1.7(PTE4/SPI1_PCS0/UART3_TX/SDHC0_D) U5.1(S\)
SPI1_PCS2: J21.4 U1.8(PTE5/SPI1_PCS2/UART3_RX/SDHC0_D)
SPI1_SCK: J21.8 R13.1 U5.6(C)
SPI1_SIN: J21.6 U1.4(PTE3/ADC1_SE7A/SPI1_SIN/U\A\R\T) U5.2(Q)
SPI1_SOUT: J21.12 U1.2(PTE1/ADC1_SE5A/SPI1_SOUT/UART1_) U5.5(D)
SWD_CLK: J18.9 U1.50(PTA0/TSI0_CH1/U\A\R\T\0\_\C\T\S)
SWD_DIO: J18.7 U1.53(PTA3/TSI0_CH4/U\A\R\T\0\_\R\T\S)
U1_L: C41.1 J3.2 R36.1 V1.1
U1_N: C41.2 J3.1 PT1.2 V1.2
U1P_IN: PT1.4 R33.1 U6.6(VINB-)
U1P_OUT: C39.1 R31.2 U1.36(ADC0_SE16/ADC0_SE21/CMP1_IN2)
U2_IN_L: C43.1 D15.A(C1) PT2.4 R37.1 R42.1 R43.1
U2_IN_N: C45.2 D16.A(C1) PT2.3 R39.1 R43.2 R44.2
U2_L: C44.1 J4.2 R41.1 V2.1
U2_N: C44.2 J4.1 PT2.2 V2.2
U2P_OUT: C42.1 R38.2 U1.27(ADC0_DP0/ADC1_DP3)
U3_IN_N: C52.2 C54.2 R54.2 U1.30(ADC1_DM0/ADC0_DM3)
U3_IN_P: C50.1 C52.1 R49.2 U1.29(ADC1_DP0/ADC0_DP3)
U3_L: C51.1 J7.2 R50.1 V3.1
U3_N: C51.2 J7.1 PT3.2 V3.2
UART1_RX: R140.1 TP22.1(PIN1) U1.106(PTC3/SPI0_PCS1/UART1_RX/FTM0_CH)
UART1_TX: R136.1 TP21.1(PIN1) U1.1(PTE0/ADC1_SE4A/SPI1_PCS1/UART1_)
USB_5V: R3.1 U1.22(VREGIN)
USB_5V_HOST: C80.1 C81.1 J11.A1(VCC) L12.2 U18.5(VCC)
USB_EN: R111.2 TP20.1(PIN1) U17.3(ENABLE)
USB_HOST_D_N: L14.1 R10.2
USB_HOST_D_P: L14.4 R9.2
USB_HOST_VBUS: C84.1 L12.1 U17.6(VOUT)
VOUT33: C17.1 C18.1 U1.21(VOUT33)
VREF_1V2: C58.1 C59.1 L10.1 TP7.1(PIN1) U8.5(VOUT_SENSE) U8.6(VOUT_FORCE)
VREF_ADC: C123.1 L9.2 L10.2 L26.2 L27.2 R162.1
VREF_ADC_HALF: C119.1 C120.1 C121.1 C122.1 CT1.2 L26.1 PT1.3 R30.2 R32.1 R35.1 R51.2 R53.1 TP44.1(PIN1) U6.3(VINA+) U6.5(VINB+) U32.1(1OUT) U32.2(1IN-) U32.6(2IN-) U32.7(2OUT)
VREF_HALF: C123.2 C124.1 R162.2 R163.1 U32.3(1IN+) U32.5(2IN+)
VREF_OUT: C11.1 C12.1 L9.1 U1.37(VREF_OUT/CMP0_IN5/ADC1_SE18/CMP)
VREFH: C13.1 C14.1 L1.1 L27.1 U1.32(VREFH)
WAKE: R81.1 R88.2 R91.2 U12.22(SD15/WAKE)
WDOG: R145.2 R147.2 U1.75(PTA24/CMP3_IN4/ULPI_DATA2/MII0_)
WIFI/LCD_GPIO1: J21.13 U1.9(PTE6/SPI1_PCS3/U\A\R\T\3\_\C\T\)
WIFI/LCD_GPIO2: J21.15 U1.10(PTE7/U\A\R\T\3\_\R\T\S\/FTM3_CH)
WIFI/LCD_GPIO3: J21.17 U1.15(PTE12/ADC3_SE17/FTM3_CH7/I2S0_T)
WIFI/LCD_GPIO4: J21.19 U1.139(PTD10/U\A\R\T\5\_\R\T\S\/FB_A18)
